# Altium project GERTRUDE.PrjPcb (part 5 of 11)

## Sheet ETH_PHY.SchDoc: ETH PHY
size A3; Author: Silvio Navaretti; CompanyName: ARDUINO; DrawnBy: Silvio Navaretti; Engineer: Silvio Navaretti; Organization: ARDUINO; SheetNumber: 36; SheetTotal: 51; RevAuthor: Silvio Navaretti
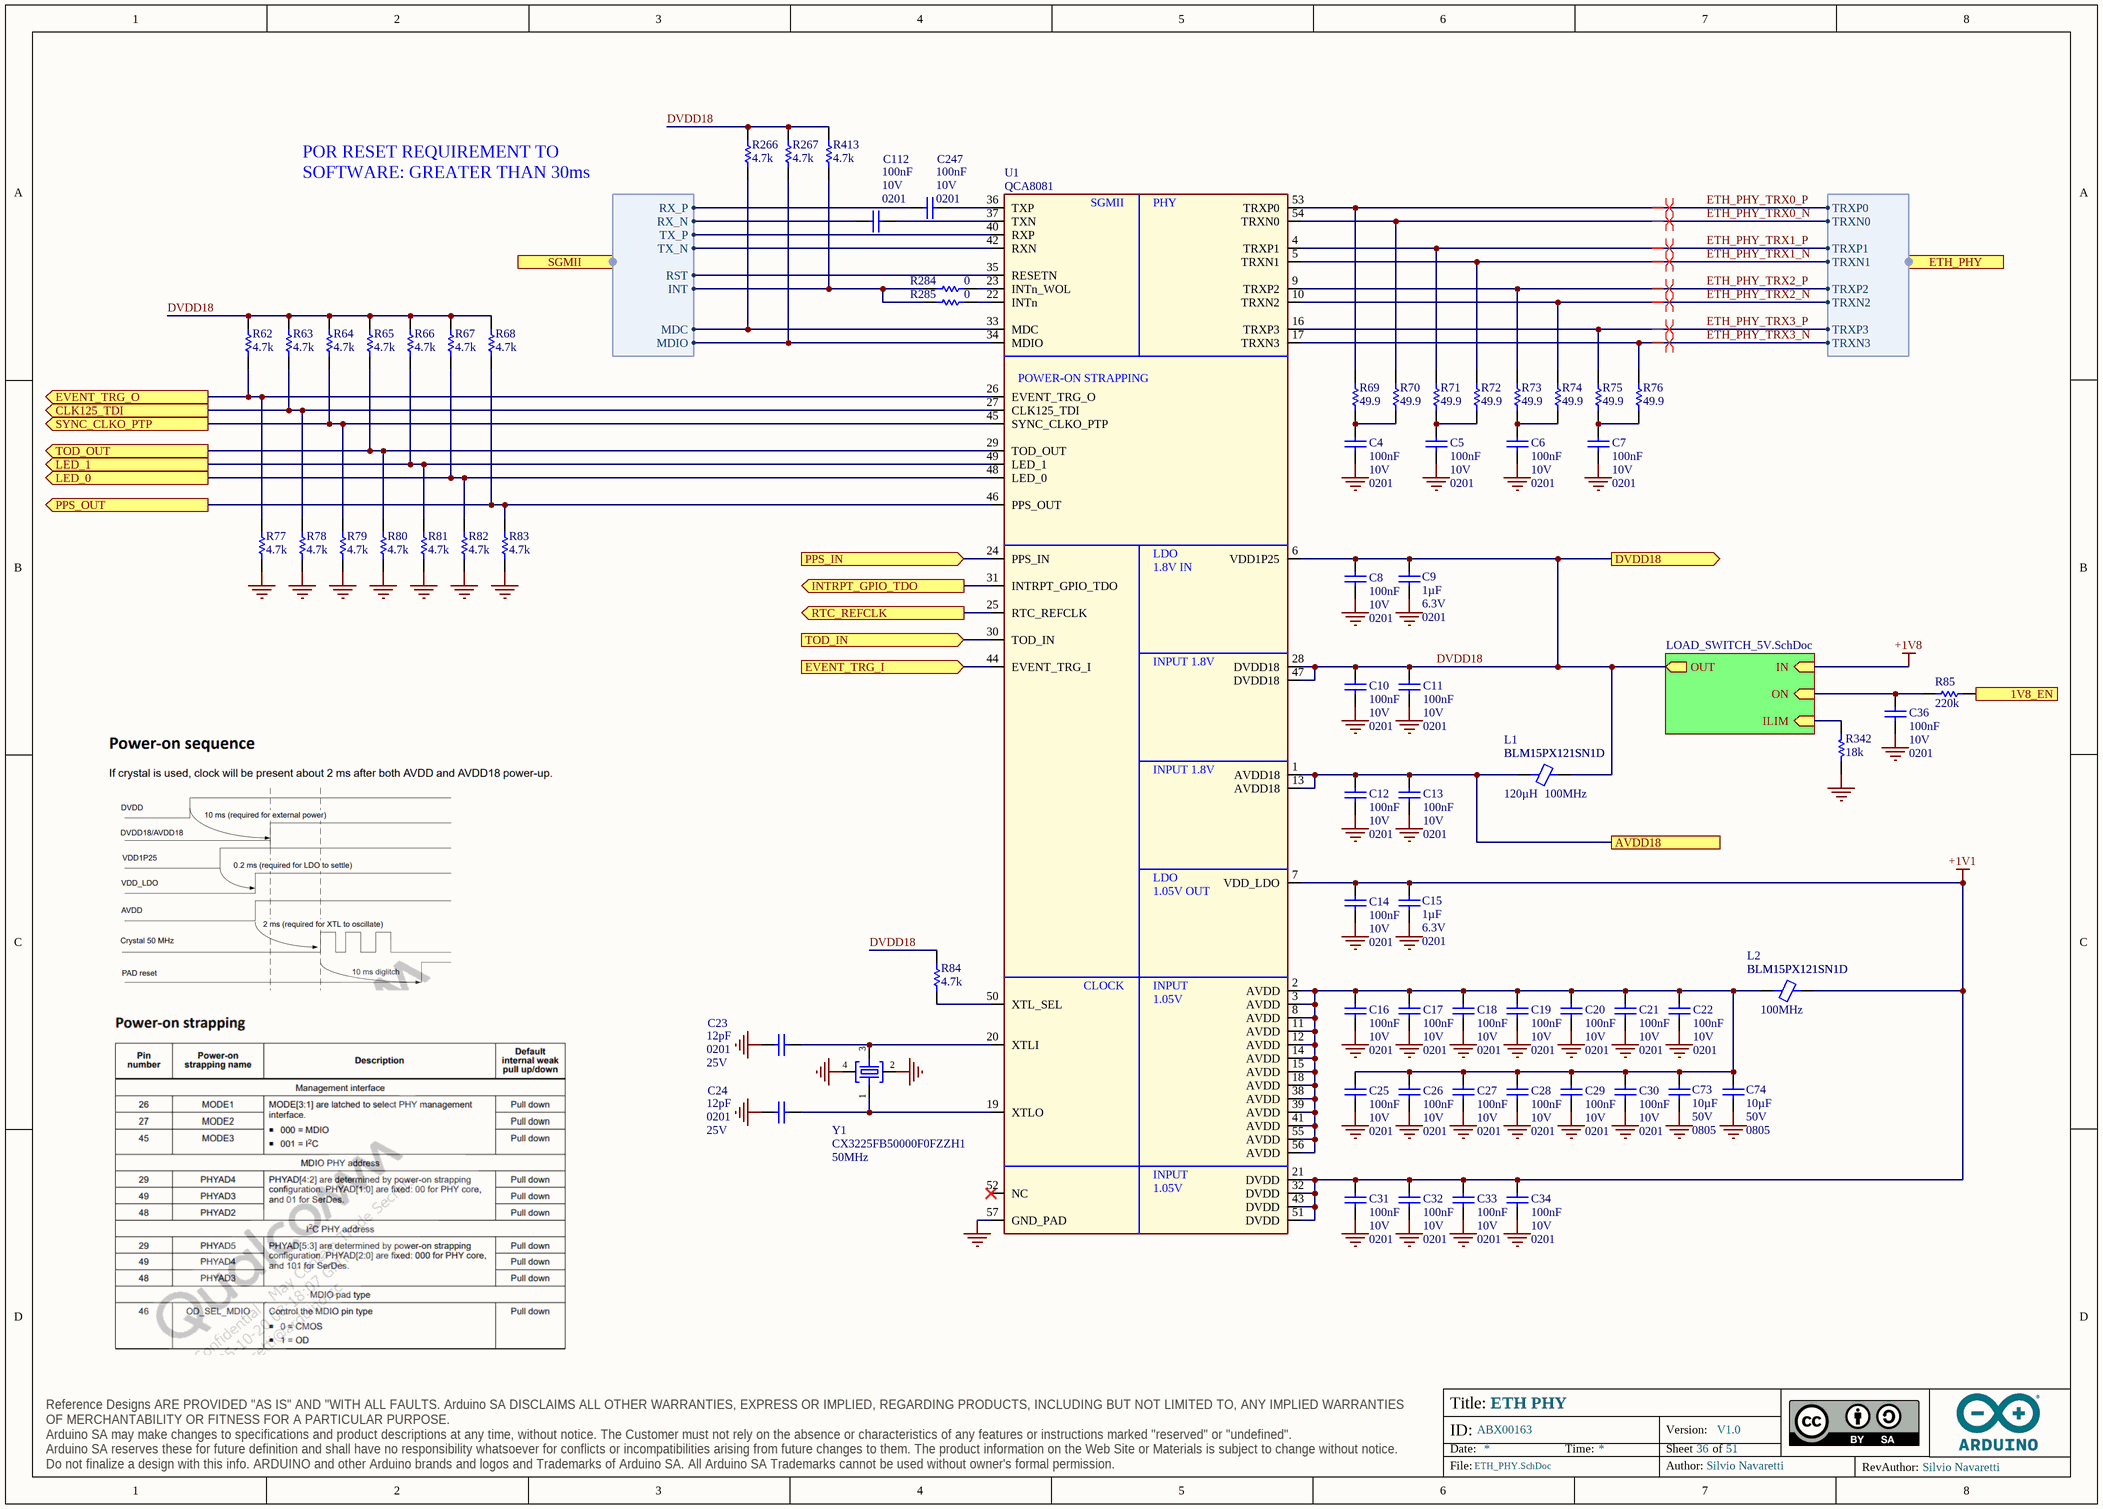
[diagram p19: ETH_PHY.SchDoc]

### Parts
C4  value 100nF  Voltage: 10V  Case Code (Imperial): 0201  [CAP-0201]  (hidden comment: CL03A104KP3NNNC)
C5  value 100nF  Voltage: 10V  Case Code (Imperial): 0201  [CAP-0201]  (hidden comment: CL03A104KP3NNNC)
C6  value 100nF  Voltage: 10V  Case Code (Imperial): 0201  [CAP-0201]  (hidden comment: CL03A104KP3NNNC)
C7  value 100nF  Voltage: 10V  Case Code (Imperial): 0201  [CAP-0201]  (hidden comment: CL03A104KP3NNNC)
C8  value 100nF  Voltage: 10V  Case Code (Imperial): 0201  [CAP-0201]  (hidden comment: CL03A104KP3NNNC)
C9  value 1µF  Voltage: 6.3V  Case Code (Imperial): 0201  [CAP-0201]  (hidden comment: GRM033R60J105MEA2D)
C10  value 100nF  Voltage: 10V  Case Code (Imperial): 0201  [CAP-0201]  (hidden comment: CL03A104KP3NNNC)
C11  value 100nF  Voltage: 10V  Case Code (Imperial): 0201  [CAP-0201]  (hidden comment: CL03A104KP3NNNC)
C12  value 100nF  Voltage: 10V  Case Code (Imperial): 0201  [CAP-0201]  (hidden comment: CL03A104KP3NNNC)
C13  value 100nF  Voltage: 10V  Case Code (Imperial): 0201  [CAP-0201]  (hidden comment: CL03A104KP3NNNC)
C14  value 100nF  Voltage: 10V  Case Code (Imperial): 0201  [CAP-0201]  (hidden comment: CL03A104KP3NNNC)
C15  value 1µF  Voltage: 6.3V  Case Code (Imperial): 0201  [CAP-0201]  (hidden comment: GRM033R60J105MEA2D)
C16  value 100nF  Voltage: 10V  Case Code (Imperial): 0201  [CAP-0201]  (hidden comment: CL03A104KP3NNNC)
C17  value 100nF  Voltage: 10V  Case Code (Imperial): 0201  [CAP-0201]  (hidden comment: CL03A104KP3NNNC)
C18  value 100nF  Voltage: 10V  Case Code (Imperial): 0201  [CAP-0201]  (hidden comment: CL03A104KP3NNNC)
C19  value 100nF  Voltage: 10V  Case Code (Imperial): 0201  [CAP-0201]  (hidden comment: CL03A104KP3NNNC)
C20  value 100nF  Voltage: 10V  Case Code (Imperial): 0201  [CAP-0201]  (hidden comment: CL03A104KP3NNNC)
C21  value 100nF  Voltage: 10V  Case Code (Imperial): 0201  [CAP-0201]  (hidden comment: CL03A104KP3NNNC)
C22  value 100nF  Voltage: 10V  Case Code (Imperial): 0201  [CAP-0201]  (hidden comment: CL03A104KP3NNNC)
C23  value 12pF  Case Code (Imperial): 0201  Voltage: 25V  [CAP-0201]  (hidden comment: GRM0335C1E120JA01J)
C24  value 12pF  Case Code (Imperial): 0201  Voltage: 25V  [CAP-0201]  (hidden comment: GRM0335C1E120JA01J)
C25  value 100nF  Voltage: 10V  Case Code (Imperial): 0201  [CAP-0201]  (hidden comment: CL03A104KP3NNNC)
C26  value 100nF  Voltage: 10V  Case Code (Imperial): 0201  [CAP-0201]  (hidden comment: CL03A104KP3NNNC)
C27  value 100nF  Voltage: 10V  Case Code (Imperial): 0201  [CAP-0201]  (hidden comment: CL03A104KP3NNNC)
C28  value 100nF  Voltage: 10V  Case Code (Imperial): 0201  [CAP-0201]  (hidden comment: CL03A104KP3NNNC)
C29  value 100nF  Voltage: 10V  Case Code (Imperial): 0201  [CAP-0201]  (hidden comment: CL03A104KP3NNNC)
C30  value 100nF  Voltage: 10V  Case Code (Imperial): 0201  [CAP-0201]  (hidden comment: CL03A104KP3NNNC)
C31  value 100nF  Voltage: 10V  Case Code (Imperial): 0201  [CAP-0201]  (hidden comment: CL03A104KP3NNNC)
C32  value 100nF  Voltage: 10V  Case Code (Imperial): 0201  [CAP-0201]  (hidden comment: CL03A104KP3NNNC)
C33  value 100nF  Voltage: 10V  Case Code (Imperial): 0201  [CAP-0201]  (hidden comment: CL03A104KP3NNNC)
C34  value 100nF  Voltage: 10V  Case Code (Imperial): 0201  [CAP-0201]  (hidden comment: CL03A104KP3NNNC)
C36  value 100nF  Voltage: 10V  Case Code (Imperial): 0201  [CAP-0201]  (hidden comment: CL03A104KP3NNNC)
C73  value 10µF  Voltage: 50V  Case Code (Imperial): 0805  [CAP-0805]  (hidden comment: GRM21BR61H106ME43L)
C74  value 10µF  Voltage: 50V  Case Code (Imperial): 0805  [CAP-0805]  (hidden comment: GRM21BR61H106ME43L)
C112  value 100nF  Voltage: 10V  Case Code (Imperial): 0201  [CAP-0201]  (hidden comment: CL03A104KP3NNNC)
C247  value 100nF  Voltage: 10V  Case Code (Imperial): 0201  [CAP-0201]  (hidden comment: CL03A104KP3NNNC)
L1  BLM15PX121SN1D  Inductance: 120µH  Test Frequency: 100MHz  [L-0402]
L2  BLM15PX121SN1D  Test Frequency: 100MHz  [L-0402]
R62  value 4.7k  [RES-0201]  (hidden comment: RC0201FR-074K7L)
R63  value 4.7k  [RES-0201]  (hidden comment: RC0201FR-074K7L)
R64  value 4.7k  [RES-0201]  (hidden comment: RC0201FR-074K7L)
R65  value 4.7k  [RES-0201]  (hidden comment: RC0201FR-074K7L)
R66  value 4.7k  [RES-0201]  (hidden comment: RC0201FR-074K7L)
R67  value 4.7k  [RES-0201]  (hidden comment: RC0201FR-074K7L)
R68  value 4.7k  [RES-0201]  (hidden comment: RC0201FR-074K7L)
R69  value 49.9  [RES-0201]  (hidden comment: AC0201FR-0749R9L)
R70  value 49.9  [RES-0201]  (hidden comment: AC0201FR-0749R9L)
R71  value 49.9  [RES-0201]  (hidden comment: AC0201FR-0749R9L)
R72  value 49.9  [RES-0201]  (hidden comment: AC0201FR-0749R9L)
R73  value 49.9  [RES-0201]  (hidden comment: AC0201FR-0749R9L)
R74  value 49.9  [RES-0201]  (hidden comment: AC0201FR-0749R9L)
R75  value 49.9  [RES-0201]  (hidden comment: AC0201FR-0749R9L)
R76  value 49.9  [RES-0201]  (hidden comment: AC0201FR-0749R9L)
R77  value 4.7k  [RES-0201]  (hidden comment: RC0201FR-074K7L)
R78  value 4.7k  [RES-0201]  (hidden comment: RC0201FR-074K7L)
R79  value 4.7k  [RES-0201]  (hidden comment: RC0201FR-074K7L)
R80  value 4.7k  [RES-0201]  (hidden comment: RC0201FR-074K7L)
R81  value 4.7k  [RES-0201]  (hidden comment: RC0201FR-074K7L)
R82  value 4.7k  [RES-0201]  (hidden comment: RC0201FR-074K7L)
R83  value 4.7k  [RES-0201]  (hidden comment: RC0201FR-074K7L)
R84  value 4.7k  [RES-0201]  (hidden comment: RC0201FR-074K7L)
R85  value 220k  [RES-0201]  (hidden comment: AC0201FR-07220KL)
R266  value 4.7k  [RES-0201]  (hidden comment: RC0201FR-074K7L)
R267  value 4.7k  [RES-0201]  (hidden comment: RC0201FR-074K7L)
R284  value 0  [RES-0201]  (hidden comment: CRCW02010000Z0ED)
R285  value 0  [RES-0201]  (hidden comment: CRCW02010000Z0ED)
R342  value 18k  [RES-0201]  (hidden comment: RC0201FR-0718KL)
R413  value 4.7k  [RES-0201]  (hidden comment: RC0201FR-074K7L)
U1  QCA8081  [Qualcomm QCA8081 56 MQFN 7x7mm pitch 0.4mm]
Y1  CX3225FB50000F0FZZH1  Frequency: 50MHz  [CRYSTAL3.2X2.5]

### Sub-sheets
U_LOAD_SWITCH_5V = LOAD_SWITCH_5V.SchDoc: IN (in), OUT (out), ON (in), ILIM (in)

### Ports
1V8_EN (in), AVDD18, CLK125_TDI (out), DVDD18 (out), ETH_PHY (harness ETH_QCA8081), EVENT_TRG_I (in), EVENT_TRG_O (out), INTRPT_GPIO_TDO (out), LED_0 (out), LED_1 (out), PPS_IN (in), PPS_OUT (out), RTC_REFCLK (out), SGMII (harness SOM_MD_SGMII0), SYNC_CLKO_PTP (out), TOD_IN (in), TOD_OUT (out)

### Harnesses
ETH_QCA8081: TRXP1, TRXN1, TRXP0, TRXN0, TRXP2, TRXN2, TRXP3, TRXN3
SOM_MD_SGMII0: RX_P, RX_N, TX_P, TX_N, RST, MDC, INT, MDIO

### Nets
+1V1: C14.2 C15.2 C31.2 C32.2 C33.2 C34.2 L2.2 U1.7(VDD_LDO) U1.21(DVDD) U1.32(DVDD) U1.43(DVDD) U1.51(DVDD)
GND: C4.1 C5.1 C6.1 C7.1 C8.1 C9.1 C10.1 C11.1 C12.1 C13.1 C14.1 C15.1 C16.1 C17.1 C18.1 C19.1 C20.1 C21.1 C22.1 C23.2 C24.2 C25.1 C26.1 C27.1 C28.1 C29.1 C30.1 C31.1 C32.1 C33.1 C34.1 C36.1 C73.2 C74.2 R77.1 R78.1 R79.1 R80.1 R81.1 R82.1 R83.1 R342.1 U1.57(GND_PAD) Y1.2 Y1.4
1V05_PG (PULLUP 1V8): R85.1 ; port 1V8_EN
DVDD18: C8.2 C9.2 C10.2 C11.2 L1.2 R62.2 R63.2 R64.2 R65.2 R66.2 R67.2 R68.2 R84.2 R266.2 R267.2 R413.2 U1.6(VDD1P25) U1.28(DVDD18) U1.47(DVDD18) ; port DVDD18, sheet U_LOAD_SWITCH_5V/OUT
ETH_PHY_TRX0_N: R70.2 U1.54(TRXN0) ; port ETH_PHY.TRXN0
ETH_PHY_TRX0_P: R69.2 U1.53(TRXP0) ; port ETH_PHY.TRXP0
ETH_PHY_TRX1_N: R72.2 U1.5(TRXN1) ; port ETH_PHY.TRXN1
ETH_PHY_TRX1_P: R71.2 U1.4(TRXP1) ; port ETH_PHY.TRXP1
ETH_PHY_TRX2_N: R74.2 U1.10(TRXN2) ; port ETH_PHY.TRXN2
ETH_PHY_TRX2_P: R73.2 U1.9(TRXP2) ; port ETH_PHY.TRXP2
ETH_PHY_TRX3_N: R76.2 U1.17(TRXN3) ; port ETH_PHY.TRXN3
ETH_PHY_TRX3_P: R75.2 U1.16(TRXP3) ; port ETH_PHY.TRXP3
GPIO_4: R284.1 R285.1 R413.1 ; port SGMII.INT
GPIO_5: R266.1 U1.33(MDC) ; port SGMII.MDC
GPIO_6: R267.1 U1.34(MDIO) ; port SGMII.MDIO
GPIO_50: U1.35(RESETN) ; port SGMII.RST
MD_SGMII0.RX_N: C112.2 ; port SGMII.RX_N
MD_SGMII0.RX_P: C247.2 ; port SGMII.RX_P
MD_SGMII0.TX_N: U1.42(RXN) ; port SGMII.TX_N
MD_SGMII0.TX_P: U1.40(RXP) ; port SGMII.TX_P
NetC4_2: C4.2 R69.1 R70.1
NetC5_2: C5.2 R71.1 R72.1
NetC6_2: C6.2 R73.1 R74.1
NetC7_2: C7.2 R75.1 R76.1
NetC12_2: C12.2 C13.2 L1.1 U1.1(AVDD18) U1.13(AVDD18) ; port AVDD18
NetC16_2: C16.2 C17.2 C18.2 C19.2 C20.2 C21.2 C22.2 C25.2 C26.2 C27.2 C28.2 C29.2 C30.2 C73.1 C74.1 L2.1 U1.2(AVDD) U1.3(AVDD) U1.8(AVDD) U1.11(AVDD) U1.12(AVDD) U1.14(AVDD) U1.15(AVDD) U1.18(AVDD) U1.38(AVDD) U1.39(AVDD) U1.41(AVDD) U1.55(AVDD) U1.56(AVDD)
NetC23_1: C23.1 U1.20(XTLI) Y1.3
NetC24_1: C24.1 U1.19(XTLO) Y1.1
NetC36_2: C36.2 R85.2 ; sheet U_LOAD_SWITCH_5V/ON
NetC112_1: C112.1 U1.37(TXN)
NetC247_1: C247.1 U1.36(TXP)
NetR62_1: R62.1 R77.2 U1.26(EVENT_TRG_O) ; port EVENT_TRG_O
NetR63_1: R63.1 R78.2 U1.27(CLK125_TDI) ; port CLK125_TDI
NetR64_1: R64.1 R79.2 U1.45(SYNC_CLKO_PTP) ; port SYNC_CLKO_PTP
NetR65_1: R65.1 R80.2 U1.29(TOD_OUT) ; port TOD_OUT
NetR66_1: R66.1 R81.2 U1.49(LED_1) ; port LED_1
NetR67_1: R67.1 R82.2 U1.48(LED_0) ; port LED_0
NetR68_1: R68.1 R83.2 U1.46(PPS_OUT) ; port PPS_OUT
NetR84_1: R84.1 U1.50(XTL_SEL)
NetR284_2: R284.2 U1.23(INTn_WOL)
NetR285_2: R285.2 U1.22(INTn)
NetR342_2: R342.2 ; sheet U_LOAD_SWITCH_5V/ILIM
NetTP40_X: U1.44(EVENT_TRG_I) ; port EVENT_TRG_I
NetTP41_X: U1.30(TOD_IN) ; port TOD_IN
NetTP42_X: U1.24(PPS_IN) ; port PPS_IN
NetTP43_X: U1.25(RTC_REFCLK) ; port RTC_REFCLK
NetTP49_X: U1.31(INTRPT_GPIO_TDO) ; port INTRPT_GPIO_TDO

Not connected (* = marked no-connect by the designer): U1 52(NC)*

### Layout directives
differential pair; differential pair class DIFF_ETHPHY; net class DIFF_ETHPHY: ETH_PHY_TRX0_N, ETH_PHY_TRX0_P, ETH_PHY_TRX1_N, ETH_PHY_TRX1_P, ETH_PHY_TRX2_N, ETH_PHY_TRX2_P, ETH_PHY_TRX3_N, ETH_PHY_TRX3_P

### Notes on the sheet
- POR RESET REQUIREMENT TO SOFTWARE: GREATER THAN 30ms

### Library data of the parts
C4-C8 C10-C14 C16-C22 C25-C34 C36 C112 C247 = C0113-A.6: CAP CHIP 0201 100nF 10% 10V X5R; Manufacturer: Samsung Electro-Mechanics; Code Arduino: C0113
C9 C15 = C0002-A.15: CAP CHIP 0201 1uF 20% 6.3V X5R; Manufacturer: Murata; Code Arduino: A5520
C23 C24 = C0003-A.15: CAP CHIP 0201 12pF 5% 25V C0G; Manufacturer: Murata; Code Arduino: C0003
C73 C74 = C0158-A.3: CAP CHIP 0805 10uF 20% 50V X5R; Manufacturer: Murata Electronics; Code Arduino: C0158
L1 = I0028-A.10: FERRITE SMD 0402 120Ohm 25% 100MHz Ferrite 2A; Manufacturer: Murata; DC Resistance (DCR): 55mR; Code Arduino: I0028; Value: 120µH
L2 = I0028-A.10: FERRITE SMD 0402 120Ohm 25% 100MHz Ferrite 2A; Manufacturer: Murata; Inductance: 120µH; DC Resistance (DCR): 55mR; Code Arduino: I0028; Value: 120µH
R62-R68 R77-R84 R266 R267 R413 = R0151-A.21: RES CHIP 0201 4k7 1% 1/20W; Manufacturer: Yageo; Temperature coefficient: 200ppm; Power: 50mW; Code Arduino: A5521
R69-R76 = R0152-A.22: RES CHIP 0201 49R9 1% 1/20W; Manufacturer: Yageo; Temperature coefficient: 200ppm; Power: 50mW; Code Arduino: R0152
R85 = R0199-A.20: RES CHIP 0201 220k 1% 1/20W; Manufacturer: Yageo; Temperature coefficient: 200ppm; Power: 50mW; Code Arduino: R0199
R284 R285 = R0140-A.21: RES CHIP 0201 0R; Manufacturer: Vishay; Temperature coefficient: 0ppm; Code Arduino: R0140; Power: 50mW; Tolerance: 0%
R342 = R0399-A.1: RES CHIP 0201 18k 1% 1/20W; Manufacturer: YAGEO; Power: 50mW; Code Arduino: R0399; Temperature Coefficient: 200ppm
U1 = U0492-A.6: IC ETH PHY 2.5Gb, 7x7mm MQFN56; Manufacturer: Qualcomm; Code Arduino: U0492
Y1 = X0031-A.3: CRYSTAL 50MHz tolerance 10ppm stability 20ppm load 10pF 3.2x2.5mm; Manufacturer: Kyocera; Code Arduino: X0031; Series Resistance: 22R

## Sheet ETH_RJ45.SchDoc: ETH RJ45
size A3; Author: Silvio Navaretti; CompanyName: ARDUINO; DrawnBy: Silvio Navaretti; Engineer: Silvio Navaretti; Organization: ARDUINO; SheetNumber: 37; SheetTotal: 51; RevAuthor: Silvio Navaretti
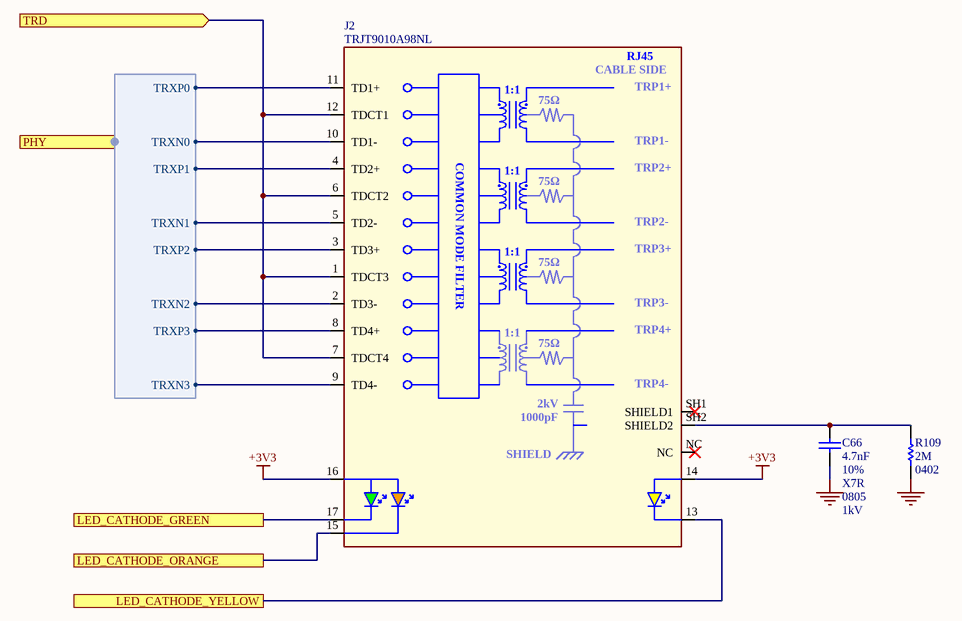
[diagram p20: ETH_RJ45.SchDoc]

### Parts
C66  value 4.7nF  Tolerance: 10%  Dielectric: X7R  Case Code (Imperial): 0805  Voltage: 1kV  [CAP-0805]  (hidden comment: FV21X472K102ECG)
J2  TRJT9010A98NL  [TRJT9010A98NL]
R109  value 2M  Case Code (Imperial): 0402  [RES-0402]  (hidden comment: RC0402FR-072ML)

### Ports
LED_CATHODE_GREEN, LED_CATHODE_ORANGE, LED_CATHODE_YELLOW, PHY (harness ETH_QCA8081), TRD (in)

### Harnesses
ETH_QCA8081: TRXP1, TRXN1, TRXP0, TRXN0, TRXP2, TRXN2, TRXP3, TRXN3

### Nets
+3V3: J2.14(YELLOW_ANODE) J2.16(COMMON_ANODE)
GND: C66.2 R109.1
ETH_PHY_TRX0_N: J2.10(TD1-) ; port PHY.TRXN0
ETH_PHY_TRX0_P: J2.11(TD1+) ; port PHY.TRXP0
ETH_PHY_TRX1_N: J2.5(TD2-) ; port PHY.TRXN1
ETH_PHY_TRX1_P: J2.4(TD2+) ; port PHY.TRXP1
ETH_PHY_TRX2_N: J2.2(TD3-) ; port PHY.TRXN2
ETH_PHY_TRX2_P: J2.3(TD3+) ; port PHY.TRXP2
ETH_PHY_TRX3_N: J2.9(TD4-) ; port PHY.TRXN3
ETH_PHY_TRX3_P: J2.8(TD4+) ; port PHY.TRXP3
NetC12_2: J2.1(TDCT3) J2.6(TDCT2) J2.7(TDCT4) J2.12(TDCT1) ; port TRD
NetC66_1: C66.1 J2.SH2(SHIELD2) R109.2
NetJ2_13: J2.13(YELLOW_CATHODE) ; port LED_CATHODE_YELLOW
NetJ2_15: J2.15(ORANGE_CATHODE) ; port LED_CATHODE_ORANGE
NetJ2_17: J2.17(GREEN_CATHODE) ; port LED_CATHODE_GREEN

Not connected (* = marked no-connect by the designer): J2 NC* SH1(SHIELD1)*

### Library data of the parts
C66 = C0059-A.14: CAP CHIP 0805 4.7nF 10% 1000V X7R; Manufacturer: PSA Shenzen; Code Arduino: 0689
J2 = J0561-A.4: CONN ETH 1x1 RJ45 TH 10/100/1000/2500 integrated magnetics, LED GREEN/YELLOW/ORANGE, micro profile 17.8x24.2x11.55mm; Manufacturer: TRXCOM; Code Arduino: J0561
R109 = R0394-A.1: RES CHIP 0402 2M 1% 1/16W; Manufacturer: YAGEO; Temperature coefficient: 100ppm; Code Arduino: R0394; Power: 62.5mW

## Sheet HEADERS_UNO.SchDoc: HEADERS UNO
size A3; Author: Silvio Navaretti; CompanyName: ARDUINO; DrawnBy: Silvio Navaretti; Engineer: Silvio Navaretti; Organization: ARDUINO; SheetNumber: 19; SheetTotal: 51; RevAuthor: Silvio Navaretti
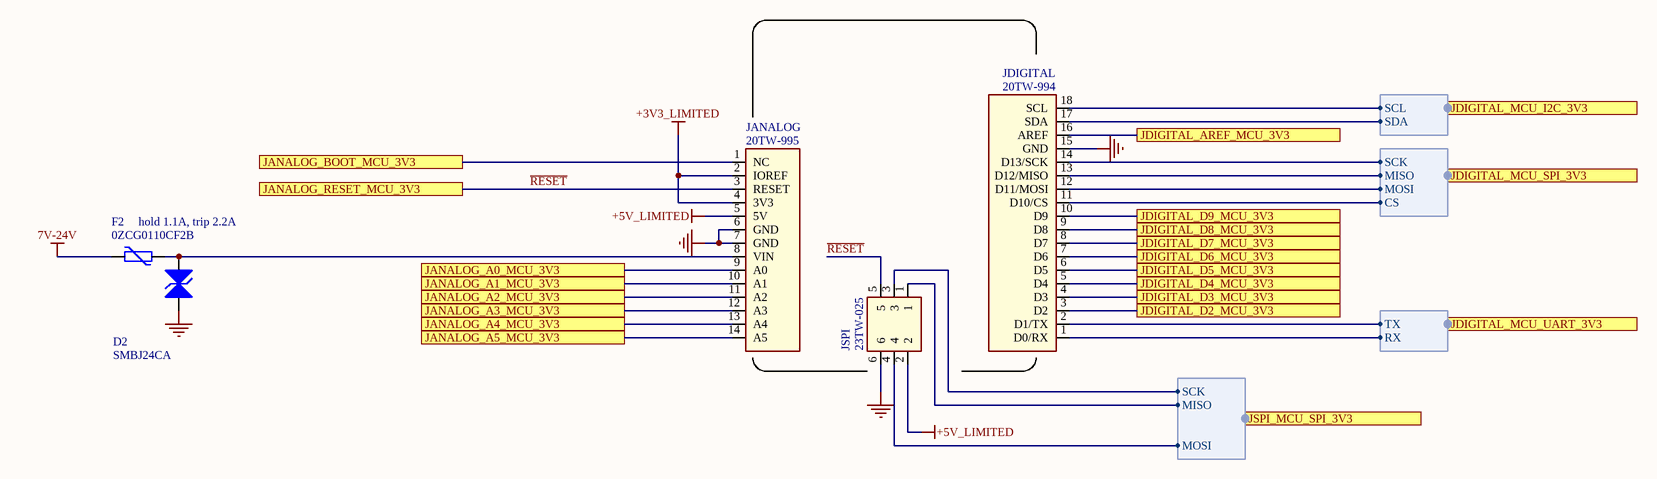
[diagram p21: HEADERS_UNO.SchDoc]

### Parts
D2  SMBJ24CA  [SMB_NOPOLARITY]
F2  0ZCG0110CF2B  [1812]
JANALOG  20TW-995  [1X14-CUSTOM]
JDIGITAL  20TW-994  [1X18-CUSTOM]
JSPI  23TW-025  [23TW-025]

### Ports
JANALOG_A0_MCU_3V3, JANALOG_A1_MCU_3V3, JANALOG_A2_MCU_3V3, JANALOG_A3_MCU_3V3, JANALOG_A4_MCU_3V3, JANALOG_A5_MCU_3V3, JANALOG_BOOT_MCU_3V3, JANALOG_RESET_MCU_3V3, JDIGITAL_AREF_MCU_3V3, JDIGITAL_D2_MCU_3V3, JDIGITAL_D3_MCU_3V3, JDIGITAL_D4_MCU_3V3, JDIGITAL_D5_MCU_3V3, JDIGITAL_D6_MCU_3V3, JDIGITAL_D7_MCU_3V3, JDIGITAL_D8_MCU_3V3, JDIGITAL_D9_MCU_3V3, JDIGITAL_MCU_I2C_3V3 (harness I2C), JDIGITAL_MCU_SPI_3V3 (harness SPI), JDIGITAL_MCU_UART_3V3 (harness UART), JSPI_MCU_SPI_3V3 (harness JSPI_SPI)

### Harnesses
SPI: SCK, MISO, MOSI, CS
UART: TX, RX
I2C: SDA, SCL
JSPI_SPI: SCK, MISO, MOSI

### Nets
7V-24V: F2.1
+3V3_LIMITED: JANALOG.2(IOREF) JANALOG.4(3V3)
+5V_LIMITED: JANALOG.5(5V) JSPI.2
GND: D2.1(A1) JANALOG.6(GND) JANALOG.7(GND) JDIGITAL.15(GND) JSPI.6
BOOT0: JANALOG.1(NC) ; port JANALOG_BOOT_MCU_3V3
PA4: JANALOG.9(A0) ; port JANALOG_A0_MCU_3V3
PA5: JANALOG.10(A1) ; port JANALOG_A1_MCU_3V3
PB0: JDIGITAL.3(D2) ; port JDIGITAL_D2_MCU_3V3
PB1: JDIGITAL.4(D3) ; port JDIGITAL_D3_MCU_3V3
PB2: JDIGITAL.7(D6) ; port JDIGITAL_D6_MCU_3V3
PB3: JDIGITAL.8(D7) ; port JDIGITAL_D7_MCU_3V3
PB4: JDIGITAL.9(D8) ; port JDIGITAL_D8_MCU_3V3
PB5: JDIGITAL.6(D5) ; port JDIGITAL_D5_MCU_3V3
PB6: JDIGITAL.5(D4) ; port JDIGITAL_D4_MCU_3V3
PB7: JDIGITAL.10(D9) ; port JDIGITAL_D9_MCU_3V3
PB10: JDIGITAL.2(D1/TX) ; port JDIGITAL_MCU_UART_3V3.TX
PB11: JDIGITAL.1(D0/RX) ; port JDIGITAL_MCU_UART_3V3.RX
PB12: JDIGITAL.11(D10/CS) ; port JDIGITAL_MCU_SPI_3V3.CS
PB13: JDIGITAL.14(D13/SCK) ; port JDIGITAL_MCU_SPI_3V3.SCK
PB14: JDIGITAL.13(D12/MISO) ; port JDIGITAL_MCU_SPI_3V3.MISO
PB15: JDIGITAL.12(D11/MOSI) ; port JDIGITAL_MCU_SPI_3V3.MOSI
PC10: JSPI.3 ; port JSPI_MCU_SPI_3V3.SCK
PC12: JSPI.4 ; port JSPI_MCU_SPI_3V3.MOSI
PE12: JANALOG.11(A2) ; port JANALOG_A2_MCU_3V3
PE13: JANALOG.12(A3) ; port JANALOG_A3_MCU_3V3
PE14: JANALOG.13(A4) ; port JANALOG_A4_MCU_3V3
PE15: JANALOG.14(A5) ; port JANALOG_A5_MCU_3V3
PF14: JSPI.1 ; port JSPI_MCU_SPI_3V3.MISO
PH11: JDIGITAL.18(SCL) ; port JDIGITAL_MCU_I2C_3V3.SCL
PH12: JDIGITAL.17(SDA) ; port JDIGITAL_MCU_I2C_3V3.SDA
~{RESET}: JANALOG.3(RESET) JSPI.5 ; port JANALOG_RESET_MCU_3V3  [project net NRST]
NetC107_2: JDIGITAL.16(AREF) ; port JDIGITAL_AREF_MCU_3V3
NetD2_2: D2.2(A2) F2.2 JANALOG.8(VIN)

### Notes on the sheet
- hold 1.1A, trip 2.2A

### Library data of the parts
D2 = D0070-A.2: TVS BIDIRECTIONAL SMD Vr 24V, Vbr min 26.7V, 600W, SMB; Manufacturer: Littlefuse; V(BR) Typ (V): 26.7; Code Arduino: D0070
F2 = P0027-A.1: PTC Ihold 1.1A Itrip 2.2A 33V 1812; Manufacturer: Bel Fuse; Code Arduino: P0027
JANALOG = J0063-A.10: JANALOG UNO header 2.54mm with 8+6 pins, custom 5.08mm pitch between them, custom silkscreen print on side; Manufacturer: 4UCONN; Code Arduino: 3649
JDIGITAL = J0035-A.13: JDIGITAL UNO header 2.54mm with 8+10 pins, custom 4.06mm pitch between them, custom silkscreen print on side; Manufacturer: 4UCONN; Code Arduino: 3648
JSPI = J0569-A.3: CONN HEADER MALE 6POS 2x3 2.54mm SMD; Manufacturer: 4UCONN; Number of Contacts: 6; Code Arduino: J0569

## Sheet POWER.SchDoc: POWER
size A3; Author: Silvio Navaretti; CompanyName: ARDUINO; DrawnBy: Silvio Navaretti; Engineer: Silvio Navaretti; Organization: ARDUINO; SheetNumber: 38; SheetTotal: 51; RevAuthor: Silvio Navaretti
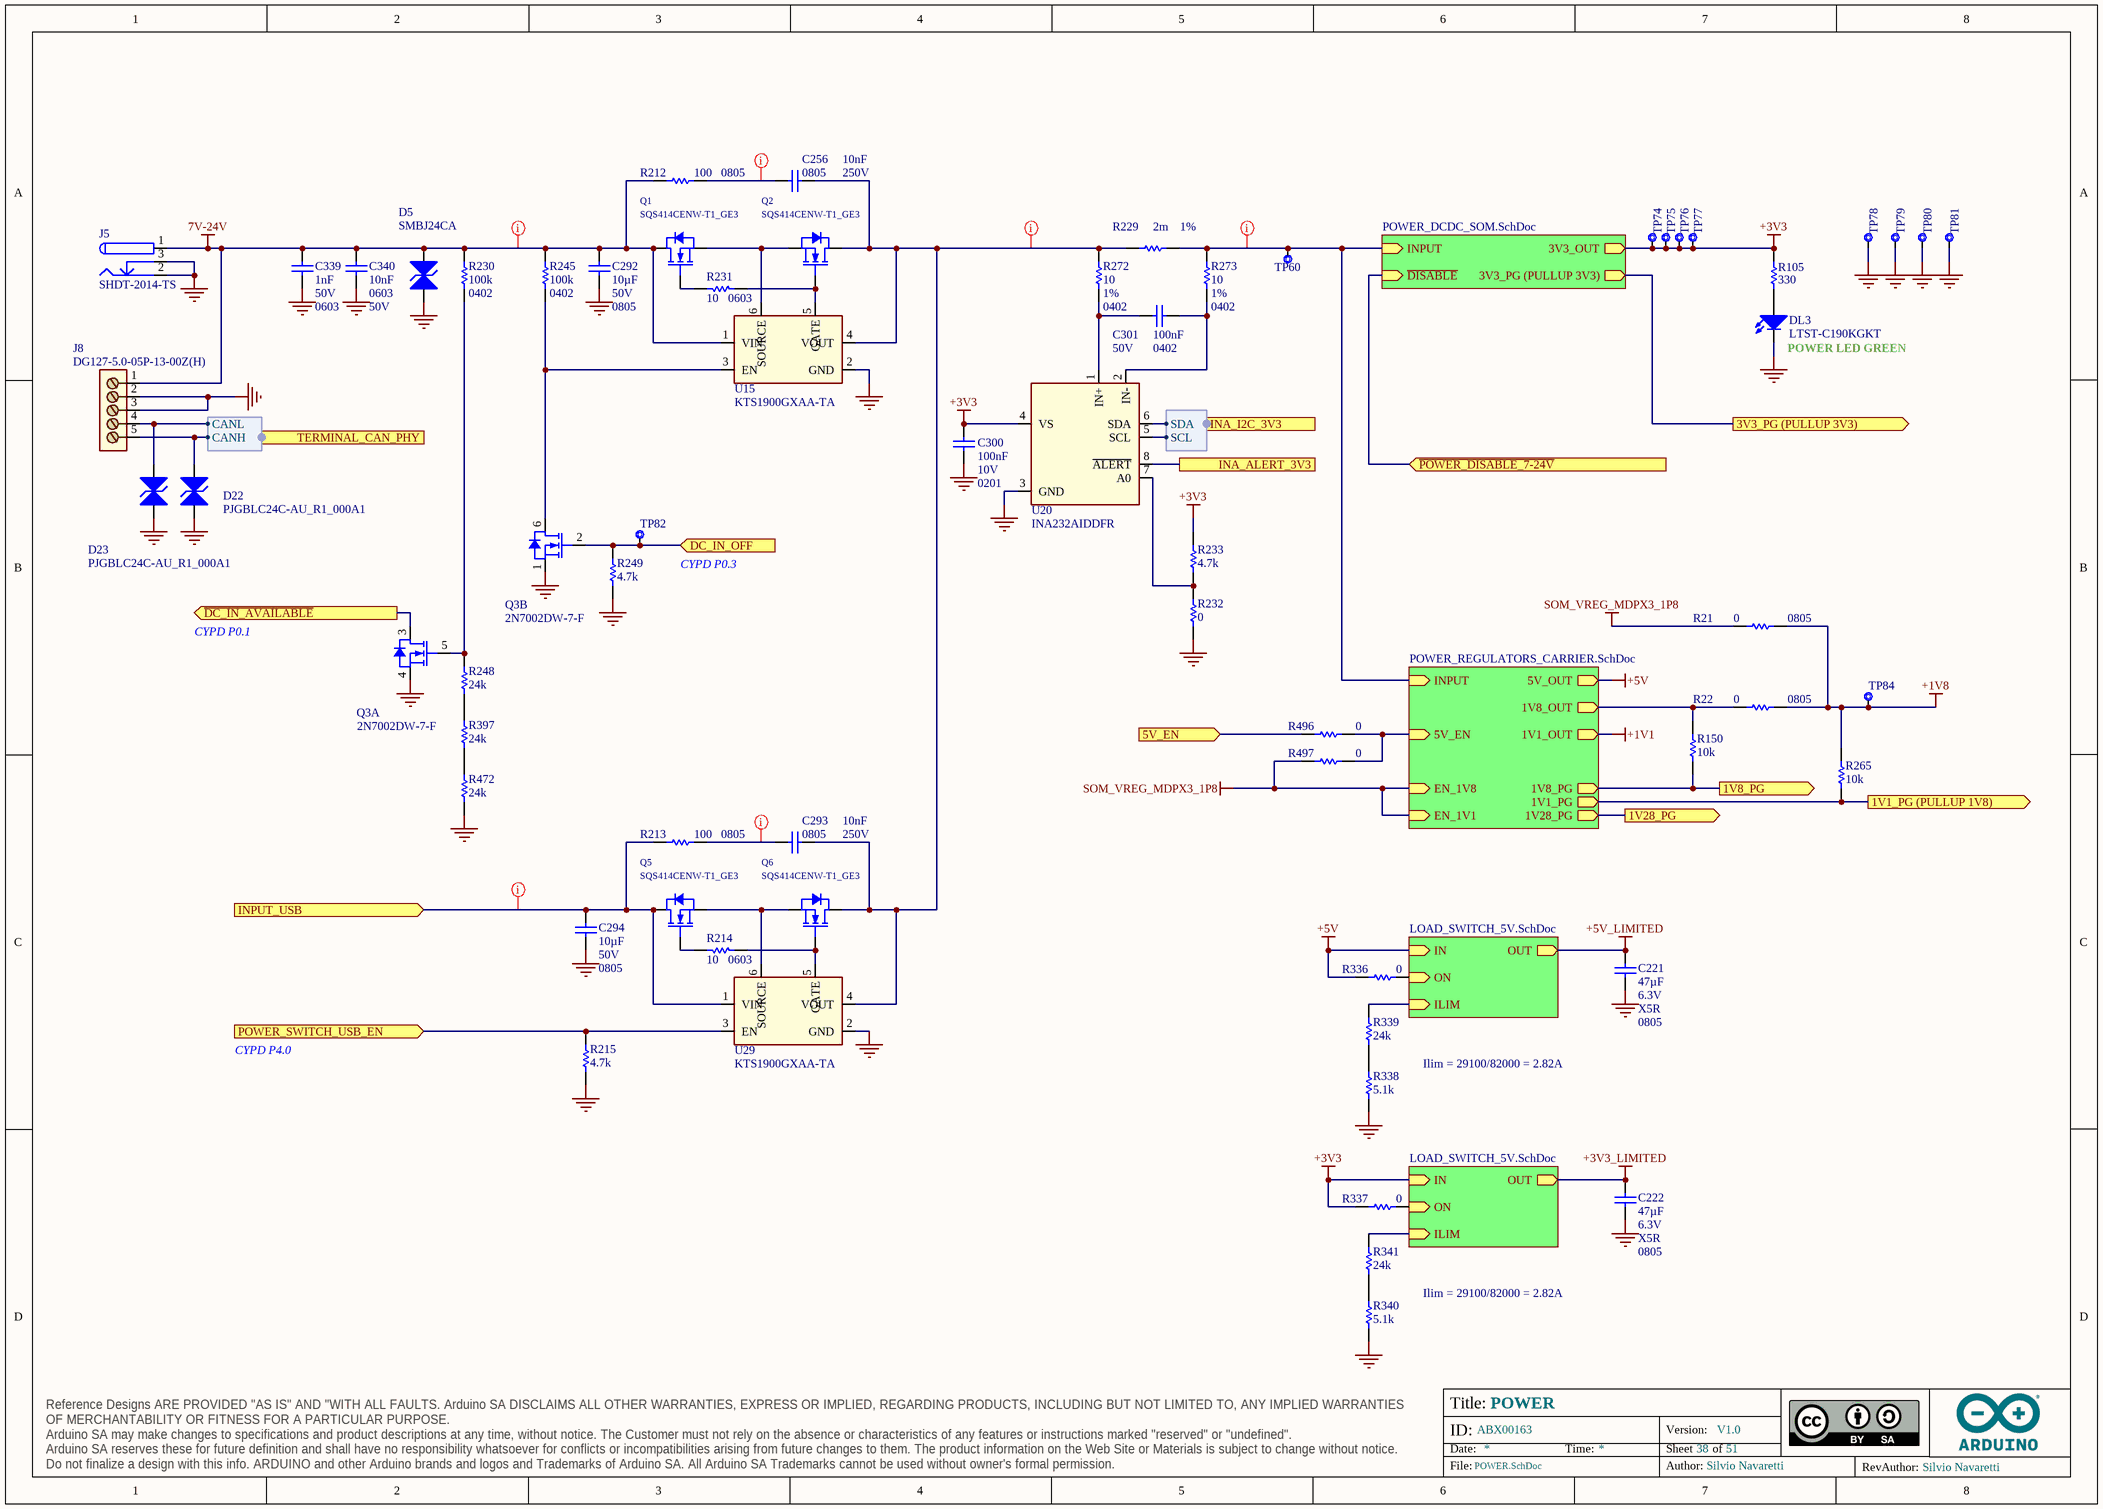
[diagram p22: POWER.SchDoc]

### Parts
C221  value 47µF  Voltage: 6.3V  Dielectric: X5R  Case Code (Imperial): 0805  [CAP-0805]  (hidden comment: C0805C476M9PAC7800)
C222  value 47µF  Voltage: 6.3V  Dielectric: X5R  Case Code (Imperial): 0805  [CAP-0805]  (hidden comment: C0805C476M9PAC7800)
C256  value 10nF  Case Code (Imperial): 0805  Voltage: 250V  [CAP-0805]  (hidden comment: GRM21BR72E103KW03L)
C292  value 10µF  Voltage: 50V  Case Code (Imperial): 0805  [CAP-0805]  (hidden comment: GRM21BR61H106ME43L)
C293  value 10nF  Case Code (Imperial): 0805  Voltage: 250V  [CAP-0805]  (hidden comment: GRM21BR72E103KW03L)
C294  value 10µF  Voltage: 50V  Case Code (Imperial): 0805  [CAP-0805]  (hidden comment: GRM21BR61H106ME43L)
C300  value 100nF  Voltage: 10V  Case Code (Imperial): 0201  [CAP-0201]  (hidden comment: CL03A104KP3NNNC)
C301  value 100nF  Voltage: 50V  Case Code (Imperial): 0402  [CAP-0402]  (hidden comment: GRM155R61H104KE19D)
C339  value 1nF  Voltage: 50V  Case Code (Imperial): 0603  [CAP-0603]  (hidden comment: CL10B102KB8WPNC)
C340  value 10nF  Case Code (Imperial): 0603  Voltage: 50V  [CAP-0603]  (hidden comment: 0603B103K500CT)
D5  SMBJ24CA  [SMB_NOPOLARITY]
D22  PJGBLC24C-AU_R1_000A1  [SOD323 NO POLARITY]
D23  PJGBLC24C-AU_R1_000A1  [SOD323 NO POLARITY]
DL3  LTST-C190KGKT  [LEDC1608X80N-AK]
J5  SHDT-2014-TS  [SHDT-2014-TS]
J8  DG127-5.0-05P-13-00Z(H)  [DG127-5.0-05P-13-00Z(H)]
Q1  SQS414CENW-T1_GE3  [SQS414CENW-T1_GE3]
Q2  SQS414CENW-T1_GE3  [SQS414CENW-T1_GE3]
Q3  2N7002DW-7-F  [SOT363]  (parts A,B of 2)
Q5  SQS414CENW-T1_GE3  [SQS414CENW-T1_GE3]
Q6  SQS414CENW-T1_GE3  [SQS414CENW-T1_GE3]
R21  value 0  Case Code (Imperial): 0805  [RES-0805]  (hidden comment: RC0805FR-070RL)
R22  value 0  Case Code (Imperial): 0805  [RES-0805]  (hidden comment: RC0805FR-070RL)
R105  value 330  [RES-0201]  (hidden comment: AC0201FR-07330RL)
R150  value 10k  [RES-0201]  (hidden comment: RC0201FR-0710KL)
R212  value 100  Case Code (Imperial): 0805  [RES-0805]  (hidden comment: RC0805FR-07100RL)
R213  value 100  Case Code (Imperial): 0805  [RES-0805]  (hidden comment: RC0805FR-07100RL)
R214  value 10  Case Code (Imperial): 0603  [RES-0603]  (hidden comment: CRCW060310R0FKEAC)
R215  value 4.7k  [RES-0201]  (hidden comment: RC0201FR-074K7L)
R229  value 2m  Tolerance: 1%  [RES-0805]  (hidden comment: PMR10EZPFV2L00)
R230  value 100k  Case Code (Imperial): 0402  [RES-0402]  (hidden comment: CRCW0402100KFKEDC)
R231  value 10  Case Code (Imperial): 0603  [RES-0603]  (hidden comment: CRCW060310R0FKEAC)
R232  value 0  [RES-0201]  (hidden comment: CRCW02010000Z0ED)
R233  value 4.7k  [RES-0201]  (hidden comment: RC0201FR-074K7L)
R245  value 100k  Case Code (Imperial): 0402  [RES-0402]  (hidden comment: CRCW0402100KFKEDC)
R248  value 24k  [RES-0201]  (hidden comment: RC0201FR-0724KL)
R249  value 4.7k  [RES-0201]  (hidden comment: RC0201FR-074K7L)
R265  value 10k  [RES-0201]  (hidden comment: RC0201FR-0710KL)
R272  value 10  Tolerance: 1%  Case Code (Imperial): 0402  [RES-0402]  (hidden comment: RC0402FR-0710RL)
R273  value 10  Tolerance: 1%  Case Code (Imperial): 0402  [RES-0402]  (hidden comment: RC0402FR-0710RL)
R336  value 0  [RES-0201]  (hidden comment: CRCW02010000Z0ED)
R337  value 0  [RES-0201]  (hidden comment: CRCW02010000Z0ED)
R338  value 5.1k  [RES-0201]  (hidden comment: ERJ-1GNF5101C)
R339  value 24k  [RES-0201]  (hidden comment: RC0201FR-0724KL)
R340  value 5.1k  [RES-0201]  (hidden comment: ERJ-1GNF5101C)
R341  value 24k  [RES-0201]  (hidden comment: RC0201FR-0724KL)
R397  value 24k  [RES-0201]  (hidden comment: RC0201FR-0724KL)
R472  value 24k  [RES-0201]  (hidden comment: RC0201FR-0724KL)
R496  value 0  [RES-0201]  (hidden comment: CRCW02010000Z0ED)
R497  value 0  [RES-0201]  (hidden comment: CRCW02010000Z0ED)
TP60  Test point 1.00mm  [TP-1.00MM]  (value not drawn)  (no BOM)
TP74  Test point 1.00mm  [TP-1.00MM]  (value not drawn)  (no BOM)
TP75  Test point 1.00mm  [TP-1.00MM]  (value not drawn)  (no BOM)
TP76  Test point 1.00mm  [TP-1.00MM]  (value not drawn)  (no BOM)
TP77  Test point 1.00mm  [TP-1.00MM]  (value not drawn)  (no BOM)
TP78  Test point 1.00mm  [TP-1.00MM]  (value not drawn)  (no BOM)
TP79  Test point 1.00mm  [TP-1.00MM]  (value not drawn)  (no BOM)
TP80  Test point 1.00mm  [TP-1.00MM]  (value not drawn)  (no BOM)
TP81  Test point 1.00mm  [TP-1.00MM]  (value not drawn)  (no BOM)
TP82  Test point 1.00mm  [TP-1.00MM]  (value not drawn)  (no BOM)
TP84  Test point 1.00mm  [TP-1.00MM]  (value not drawn)  (no BOM)
U15  KTS1900GXAA-TA  [SOT23-6 PITCH 0.95]
U20  INA232AIDDFR  [TI DDF SOT23-THIN 8 pin 1.6x2.9x1.1 mm heigth]
U29  KTS1900GXAA-TA  [SOT23-6 PITCH 0.95]

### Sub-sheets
U_LOAD_SWITCH_5V = LOAD_SWITCH_5V.SchDoc: IN (in), OUT (out), ON (in), ILIM (in)
U_LOAD_SWITCH_5V = LOAD_SWITCH_5V.SchDoc: IN (in), OUT (out), ON (in), ILIM (in)
U_POWER_DCDC_CARRIER = POWER_REGULATORS_CARRIER.SchDoc: INPUT (in), 5V_EN (in), 1V8_PG (out), 1V8_OUT (out), 1V1_OUT (out), 5V_OUT (out), 1V28_PG (out), 1V1_PG (out), EN_1V8 (in), EN_1V1 (in)
U_POWER_SOM = POWER_DCDC_SOM.SchDoc: 3V3_OUT (out), INPUT (in), ~{DISABLE} (in), 3V3_PG (PULLUP 3V3) (out)

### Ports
1V1_PG (PULLUP 1V8) (out), 1V8_PG (out), 1V28_PG (out), 3V3_PG (PULLUP 3V3) (out), 5V_EN (in), DC_IN_OFF (in), INA_ALERT_3V3, INA_I2C_3V3 (harness I2C), INPUT_USB (in), POWER_SWITCH_USB_EN (in), TERMINAL_CAN_PHY (harness CAN_PHY), ~{DC_IN_AVAILABLE} (out), ~{POWER_DISABLE_7-24V} (in)

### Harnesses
CAN_PHY: CANH, CANL
I2C: SDA, SCL

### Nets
7V-24V: C292.2 C339.1 C340.1 D5.2(A2) J5.1 J8.1 Q1.D R212.2 R230.1 R245.1 U15.1(VIN)
+1V8: R21.2 R22.2 R265.1 TP84.X
+3V3: C300.2 R105.2 R233.1 R337.1 TP74.X TP75.X TP76.X TP77.X U20.4(VS) ; sheet U_POWER_SOM/3V3_OUT, sheet U_LOAD_SWITCH_5V/IN
+3V3_LIMITED: C222.2 ; sheet U_LOAD_SWITCH_5V/OUT
+5V: R336.1 ; sheet U_POWER_DCDC_CARRIER/5V_OUT, sheet U_LOAD_SWITCH_5V/IN
+5V_LIMITED: C221.2 ; sheet U_LOAD_SWITCH_5V/OUT
GND: C221.1 C222.1 C292.1 C294.1 C300.1 C339.2 C340.2 D5.1(A1) D22.1(A1) D23.1(A1) DL3.C J5.2 J5.3 J8.2 J8.3 Q3.1(S) Q3.4(S) R215.2 R232.1 R249.2 R338.1 R340.1 R472.1 TP78.X TP79.X TP80.X TP81.X U15.2(GND) U20.3(GND) U29.2(GND)
SOM_VREG_MDPX3_1P8: R21.1 R497.2 ; sheet U_POWER_DCDC_CARRIER/EN_1V8, sheet U_POWER_DCDC_CARRIER/EN_1V1
1V05_PG (PULLUP 1V8): R265.2 ; port 1V1_PG (PULLUP 1V8), sheet U_POWER_DCDC_CARRIER/1V1_PG
3V3_PG (PULLUP 3V3): port 3V3_PG (PULLUP 3V3), sheet U_POWER_SOM/3V3_PG (PULLUP 3V3)
MD_GPIO_49: R496.2 ; port 5V_EN
MD_QUP1_SE4_I2C_3V3.SCL: U20.5(SCL) ; port INA_I2C_3V3.SCL
MD_QUP1_SE4_I2C_3V3.SDA: U20.6(SDA) ; port INA_I2C_3V3.SDA
~{POWER_DISABLE_7-24V}: port ~{POWER_DISABLE_7-24V}, sheet U_POWER_SOM/~{DISABLE}
PA_VBUS: C294.2 Q5.D R213.2 U29.1(VIN) ; port INPUT_USB
NetC76_1: R229.2 R273.2 TP60.X ; sheet U_POWER_SOM/INPUT, sheet U_POWER_DCDC_CARRIER/INPUT
NetC119_2: R22.1 R150.1 ; sheet U_POWER_DCDC_CARRIER/1V8_OUT
NetC256_1: C256.1 R212.1
NetC256_2: C256.2 C293.2 Q2.D Q6.D R229.1 R272.2 U15.4(VOUT) U29.4(VOUT)
NetC293_1: C293.1 R213.1
NetC301_1: C301.1 R272.1 U20.1(IN+)
NetC301_2: C301.2 R273.1 U20.2(IN-)
NetC342_1: D22.2(A2) J8.5 ; port TERMINAL_CAN_PHY.CANH
NetC345_2: R496.1 R497.1 ; sheet U_POWER_DCDC_CARRIER/5V_EN
NetC361_1: D23.2(A2) J8.4 ; port TERMINAL_CAN_PHY.CANL
NetDL3_A: DL3.A R105.1
NetQ1_G: Q1.G R231.2
NetQ1_S: Q1.S Q2.S U15.6(SOURCE)
NetQ2_G: Q2.G R231.1 U15.5(GATE)
NetQ3_2: Q3.2(G) R249.1 TP82.X ; port DC_IN_OFF
NetQ3_3: Q3.3(D) ; port ~{DC_IN_AVAILABLE}
NetQ3_5: Q3.5(G) R230.2 R248.2
NetQ3_6: Q3.6(D) R245.2 U15.3(EN)
NetQ5_G: Q5.G R214.2
NetQ5_S: Q5.S Q6.S U29.6(SOURCE)
NetQ6_G: Q6.G R214.1 U29.5(GATE)
NetR150_2: R150.2 ; port 1V8_PG, sheet U_POWER_DCDC_CARRIER/1V8_PG
NetR215_1: R215.1 U29.3(EN) ; port POWER_SWITCH_USB_EN
NetR232_2: R232.2 R233.2 U20.7(A0)
NetR248_1: R248.1 R397.2
NetR336_2: R336.2 ; sheet U_LOAD_SWITCH_5V/ON
NetR337_2: R337.2 ; sheet U_LOAD_SWITCH_5V/ON
NetR338_2: R338.2 R339.1
NetR339_2: R339.2 ; sheet U_LOAD_SWITCH_5V/ILIM
NetR340_2: R340.2 R341.1
NetR341_2: R341.2 ; sheet U_LOAD_SWITCH_5V/ILIM
NetR397_1: R397.1 R472.2
NetU18_5: port 1V28_PG, sheet U_POWER_DCDC_CARRIER/1V28_PG
NetU20_8: U20.8(~{ALERT}) ; port INA_ALERT_3V3

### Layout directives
net class HIGH_CLEARANCE: 7V-24V, NetC76_1, NetC256_1, NetC256_2, NetC293_1, PA_VBUS

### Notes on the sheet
- (near DL3) POWER LED GREEN
- CYPD P0.3
- CYPD P0.1
- CYPD P4.0
- Ilim = 29100/82000 = 2.82A

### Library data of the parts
C221 C222 = C0199-A.1: CAP CHIP 0805 47uF 20% 6.3V X5R; Manufacturer: KEMET; Code Arduino: C0199
C256 C293 = C0209-A.1: CAP CHIP 0805 10nF 250V X7R; Manufacturer: Murata; Tolerance: 10%; Code Arduino: C0209
C292 C294 = C0158-A.3: as C73 on sheet ETH_PHY
C300 = C0113-A.6: as C4-C8 on sheet ETH_PHY
C301 = C0015-A.14: CAP CHIP 0402 100nF 10% 50V X5R; Manufacturer: Murata; Code Arduino: A5141
C339 = C0063-A.3: CAP CHIP 0603 1nF 10% 50V X7R; Manufacturer: Samsung Electro-Mechanics; Code Arduino: C0063
C340 = C0040-A.14: CAP CHIP 0603 10nF 10% 50V X7R; Manufacturer: Walsin; Code Arduino: 0142
D5 = D0070-A.2: as D2 on sheet HEADERS_UNO
D22 D23 = D0098-A.2: TVS BIDIRECTIONAL SMD Vr 24V, Vbr min 27.27V, 350W, SOD-323; V(BR) Typ (V): 26.7; Code Arduino: D0098
DL3 = L0009-A.6: LED SMD 0603 GREEN/568 15mcd 120^; Manufacturer: Liteon; Code Arduino: 2204
J5 = J0579-A.2: CONN PWR JACK TH 2.1X5.5mm 1.6mm PCB; Manufacturer: POWERWAY; Code Arduino: J0579
J8 = J0563-A.5: CONN SCREW TERMINAL 5 POS pitch 5mm height 13.6mm BLACK; Manufacturer: Degson; Code Arduino: J0563
Q1 Q2 Q5 Q6 = T0065-2: MOSFET N-CH 60V 18A PowerPAK 1212-8W 3.3x3.3mm; Manufacturer: Vishay; Code Arduino: T0065
Q3 = T0011-A.12: MOSFET 2N-CH 60V 0.32A SOT363; Manufacturer: Diodes Inc.; Device Type: Mosfet 2N-CH SMD; Code Arduino: A5500
R21 R22 = R0323-A.1: RES CHIP 0805 0R 1% 1/8W; Manufacturer: YAGEO; Code Arduino: R0323; Power: 125mW; Temperature coefficient: 0ppm
R105 = R0149-A.21: RES CHIP 0201 330R 1% 1/20W; Manufacturer: Yageo; Power: 50mW; Code Arduino: R0149; Temperature coefficient: 200ppm
R150 R265 = R0145-A.21: RES CHIP 0201 10k 1% 1/20W; Manufacturer: Yageo; Power: 50mW; Temperature coefficient: 200ppm; Code Arduino: R0145
R212 R213 = R0130-A.14: RES CHIP 0805 100R 1% 1/8W 100ppm; Manufacturer: YAGEO; Power: 125mW; Code Arduino: R0130
R214 R231 = R0188-A.20: RES CHIP 0603 10R 1% 1/10W; Manufacturer: Vishay; Temperature coefficient: 100ppm; Code Arduino: R0188; Power: 100mW
R215 R233 R249 = R0151-A.21: as R62-R68 on sheet ETH_PHY
R229 = R0132-A.12: RES CHIP 0805 2mR 1% 1/2W; Manufacturer: ROHM Semiconductor; Power: 500mW; Code Arduino: A5411; Temperature coefficient: 150ppm
R230 R245 = R0001-A.24: RES CHIP 0402 100k 1% 1/16W; Manufacturer: Vishay; Power: 62.5mW; Code Arduino: 0134; Temperature coefficient: 100ppm
R232 R336 R337 R496 R497 = R0140-A.21: as R284 on sheet ETH_PHY
R248 R397 R472 = R0398-A.1: RES CHIP 0201 24k 1% 1/20W; Manufacturer: YAGEO; Power: 50mW; Code Arduino: R0398; Temperature Coefficient: 200ppm
R272 R273 = R0170-A.23: RES CHIP 0402 10R 1% 1/16W; Manufacturer: YAGEO; Power: 62.5mW; Temperature coefficient: 200ppm; Code Arduino: R0170
R338 R340 = R0376-A.1: RES CHIP 0201 5k1 1% 1/20W; Manufacturer: Panasonic; Code Arduino: R0376; Power: 50mW; Temperature Coefficient: 200ppm
R339 R341 = R0398-A.1: RES CHIP 0201 24k 1% 1/20W; Manufacturer: YAGEO; Code Arduino: R0398; Power: 50mW; Temperature Coefficient: 200ppm
TP60 TP74-TP82 TP84 = UT0013-A.6: Part Number: This is not a component
U15 U29 = U0502-A.3: IC Ideal diode and load switch controller with reverse input protection, 4.2V to 60V, EN pin 1.32V, SOT23-6; Manufacturer: Kinetic Technology; Code Arduino: U0502
U20 = U0519-A.2: IC MONITOR PWR/CURR/VOLT 16bit ADC I2C SOT23-THIN8 1.6x2.9x1.1 mm; Manufacturer: Texas Instruments; Code Arduino: U0519

## Sheet POWER_DCDC_SOM.SchDoc: POWER DCDC SOM
size A3; Author: Silvio Navaretti; CompanyName: ARDUINO; DrawnBy: Silvio Navaretti; Engineer: Silvio Navaretti; Organization: ARDUINO; SheetNumber: 39; SheetTotal: 51; RevAuthor: Silvio Navaretti
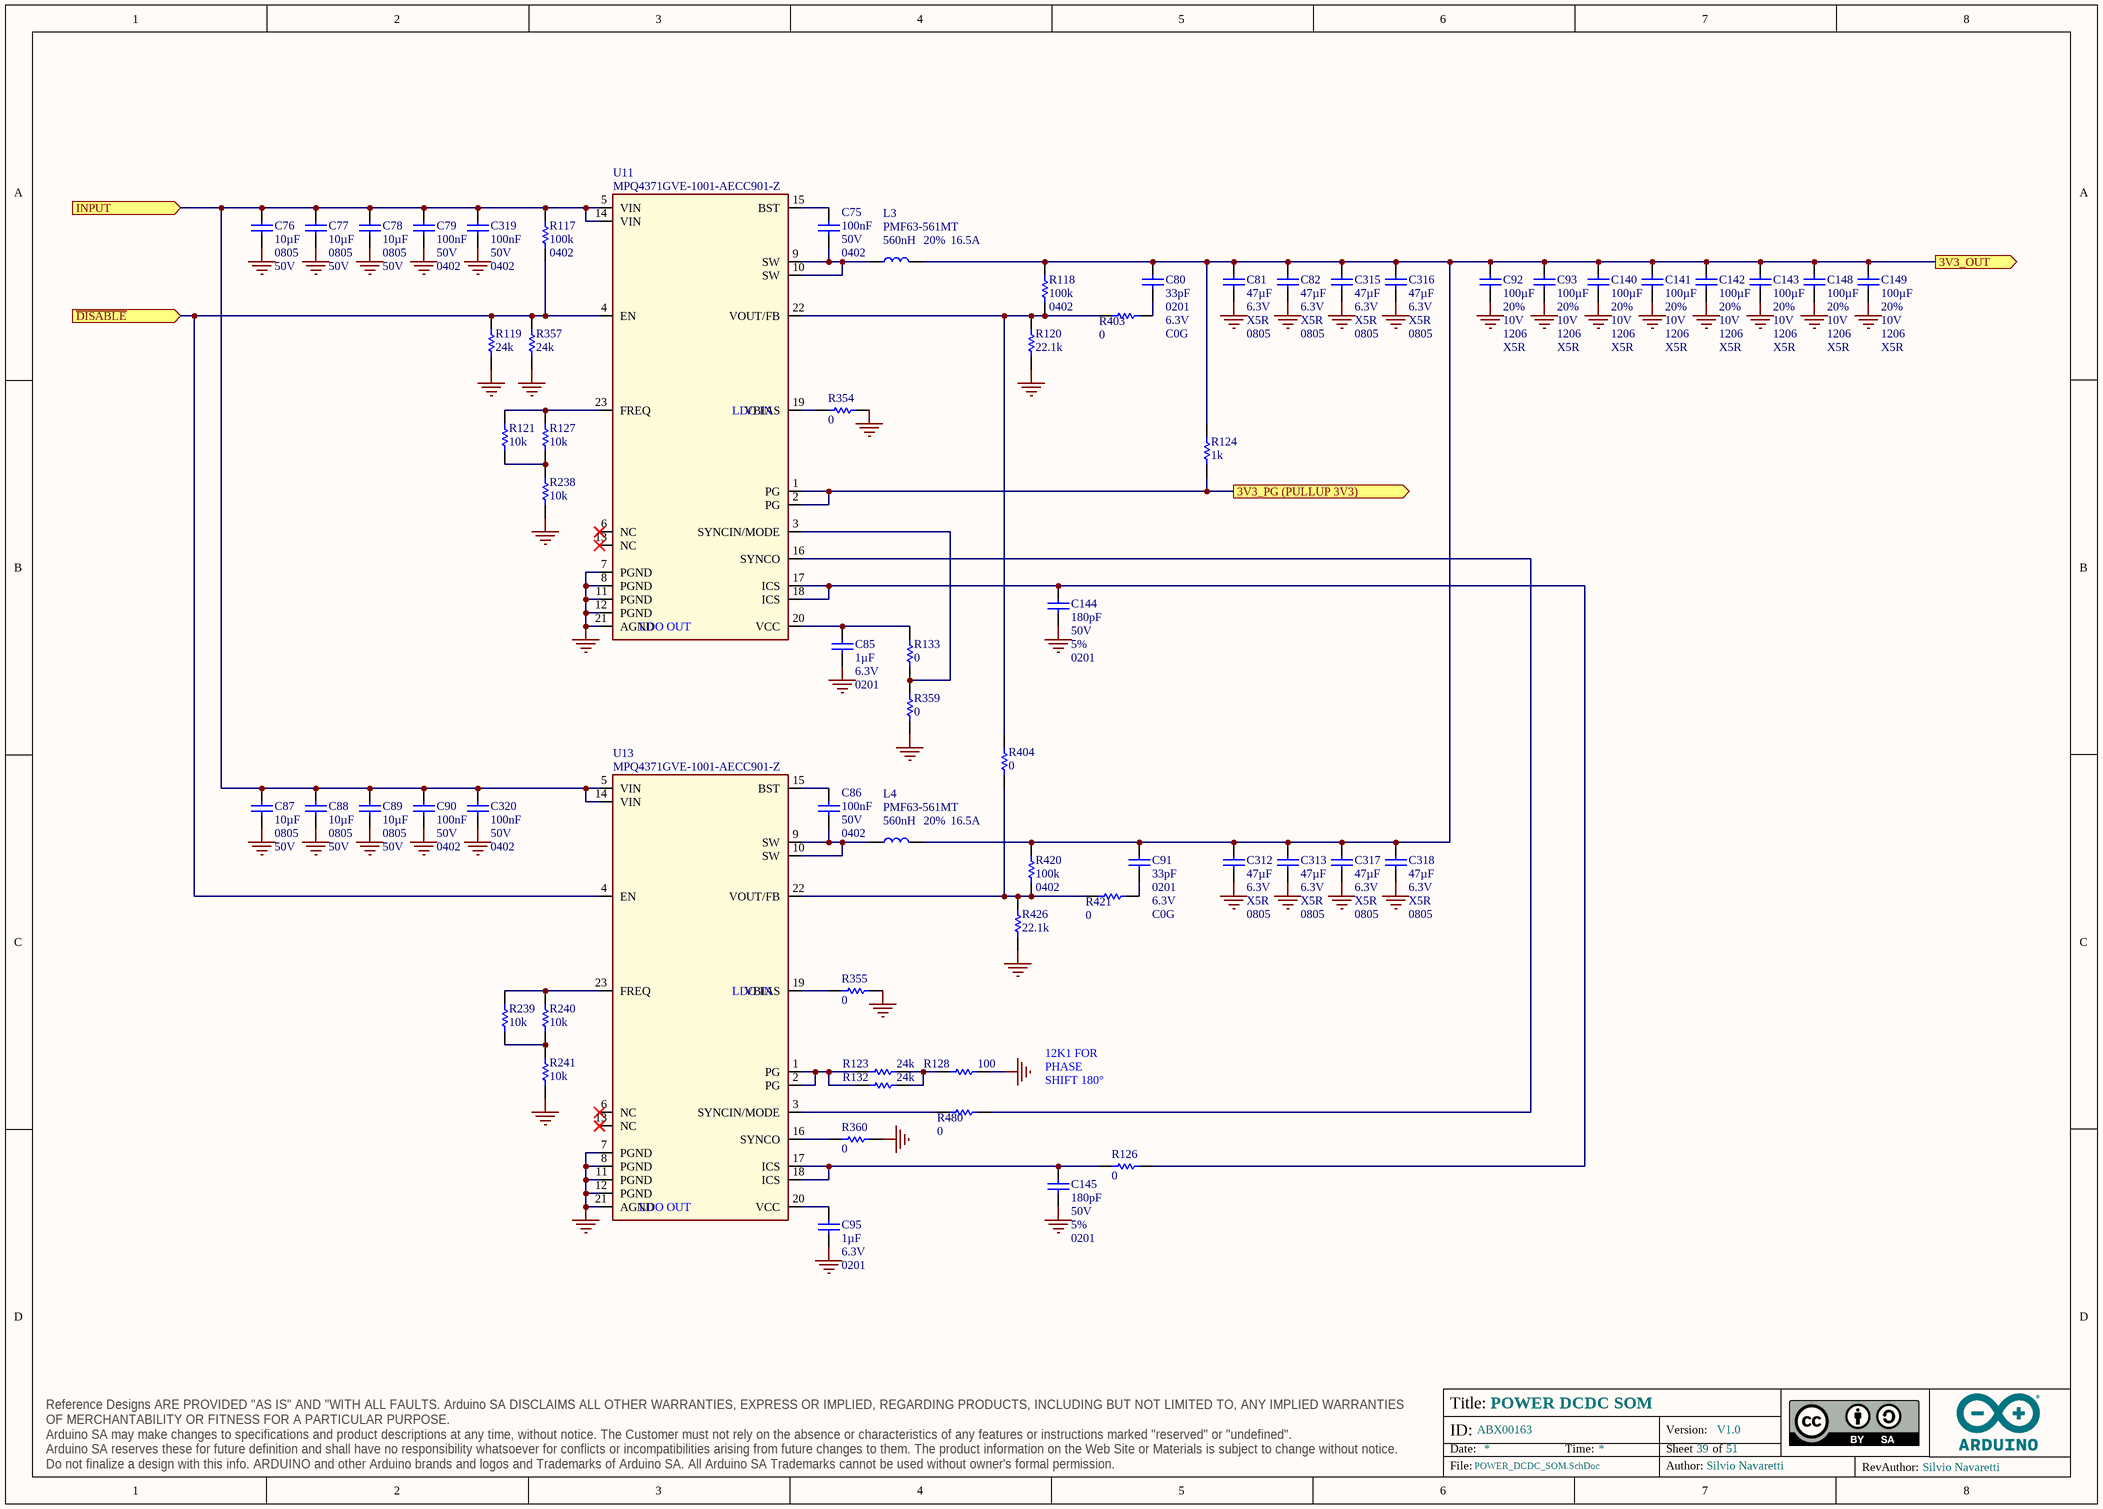
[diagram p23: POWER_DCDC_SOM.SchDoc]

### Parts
C75  value 100nF  Voltage: 50V  Case Code (Imperial): 0402  [CAP-0402]  (hidden comment: GRM155R61H104KE19D)
C76  value 10µF  Case Code (Imperial): 0805  Voltage: 50V  [CAP-0805]  (hidden comment: GRM21BR61H106ME43L)
C77  value 10µF  Case Code (Imperial): 0805  Voltage: 50V  [CAP-0805]  (hidden comment: GRM21BR61H106ME43L)
C78  value 10µF  Case Code (Imperial): 0805  Voltage: 50V  [CAP-0805]  (hidden comment: GRM21BR61H106ME43L)
C79  value 100nF  Voltage: 50V  Case Code (Imperial): 0402  [CAP-0402]  (hidden comment: GRM155R61H104KE19D)
C80  value 33pF  Case Code (Imperial): 0201  Voltage: 6.3V  Dielectric: C0G  [CAP-0201]  (hidden comment: GJM0335C0J330JB01J)
C81  value 47µF  Voltage: 6.3V  Dielectric: X5R  Case Code (Imperial): 0805  [CAP-0805]  (hidden comment: C0805C476M9PAC7800)
C82  value 47µF  Voltage: 6.3V  Dielectric: X5R  Case Code (Imperial): 0805  [CAP-0805]  (hidden comment: C0805C476M9PAC7800)
C85  value 1µF  Voltage: 6.3V  Case Code (Imperial): 0201  [CAP-0201]  (hidden comment: GRM033R60J105MEA2D)
C86  value 100nF  Voltage: 50V  Case Code (Imperial): 0402  [CAP-0402]  (hidden comment: GRM155R61H104KE19D)
C87  value 10µF  Case Code (Imperial): 0805  Voltage: 50V  [CAP-0805]  (hidden comment: GRM21BR61H106ME43L)
C88  value 10µF  Case Code (Imperial): 0805  Voltage: 50V  [CAP-0805]  (hidden comment: GRM21BR61H106ME43L)
C89  value 10µF  Case Code (Imperial): 0805  Voltage: 50V  [CAP-0805]  (hidden comment: GRM21BR61H106ME43L)
C90  value 100nF  Voltage: 50V  Case Code (Imperial): 0402  [CAP-0402]  (hidden comment: GRM155R61H104KE19D)
C91  value 33pF  Case Code (Imperial): 0201  Voltage: 6.3V  Dielectric: C0G  [CAP-0201]  (hidden comment: GJM0335C0J330JB01J)
C92  value 100µF  Tolerance: 20%  Voltage: 10V  Case Code (Imperial): 1206  Dielectric: X5R  [CAP-1206]  (hidden comment: GRM31CR61A107MEA8L)
C93  value 100µF  Tolerance: 20%  Voltage: 10V  Case Code (Imperial): 1206  Dielectric: X5R  [CAP-1206]  (hidden comment: GRM31CR61A107MEA8L)
C95  value 1µF  Voltage: 6.3V  Case Code (Imperial): 0201  [CAP-0201]  (hidden comment: GRM033R60J105MEA2D)
C140  value 100µF  Tolerance: 20%  Voltage: 10V  Case Code (Imperial): 1206  Dielectric: X5R  [CAP-1206]  (hidden comment: GRM31CR61A107MEA8L)
C141  value 100µF  Tolerance: 20%  Voltage: 10V  Case Code (Imperial): 1206  Dielectric: X5R  [CAP-1206]  (hidden comment: GRM31CR61A107MEA8L)
C142  value 100µF  Tolerance: 20%  Voltage: 10V  Case Code (Imperial): 1206  Dielectric: X5R  [CAP-1206]  (hidden comment: GRM31CR61A107MEA8L)
C143  value 100µF  Tolerance: 20%  Voltage: 10V  Case Code (Imperial): 1206  Dielectric: X5R  [CAP-1206]  (hidden comment: GRM31CR61A107MEA8L)
C144  value 180pF  Voltage: 50V  Tolerance: 5%  Case Code (Imperial): 0201  [CAP-0201]  (hidden comment: GRM0335C1H181JA01D)
C145  value 180pF  Voltage: 50V  Tolerance: 5%  Case Code (Imperial): 0201  [CAP-0201]  (hidden comment: GRM0335C1H181JA01D)
C148  value 100µF  Tolerance: 20%  Voltage: 10V  Case Code (Imperial): 1206  Dielectric: X5R  [CAP-1206]  (hidden comment: GRM31CR61A107MEA8L)
C149  value 100µF  Tolerance: 20%  Voltage: 10V  Case Code (Imperial): 1206  Dielectric: X5R  [CAP-1206]  (hidden comment: GRM31CR61A107MEA8L)
C312  value 47µF  Voltage: 6.3V  Dielectric: X5R  Case Code (Imperial): 0805  [CAP-0805]  (hidden comment: C0805C476M9PAC7800)
C313  value 47µF  Voltage: 6.3V  Dielectric: X5R  Case Code (Imperial): 0805  [CAP-0805]  (hidden comment: C0805C476M9PAC7800)
C315  value 47µF  Voltage: 6.3V  Dielectric: X5R  Case Code (Imperial): 0805  [CAP-0805]  (hidden comment: C0805C476M9PAC7800)
C316  value 47µF  Voltage: 6.3V  Dielectric: X5R  Case Code (Imperial): 0805  [CAP-0805]  (hidden comment: C0805C476M9PAC7800)
C317  value 47µF  Voltage: 6.3V  Dielectric: X5R  Case Code (Imperial): 0805  [CAP-0805]  (hidden comment: C0805C476M9PAC7800)
C318  value 47µF  Voltage: 6.3V  Dielectric: X5R  Case Code (Imperial): 0805  [CAP-0805]  (hidden comment: C0805C476M9PAC7800)
C319  value 100nF  Voltage: 50V  Case Code (Imperial): 0402  [CAP-0402]  (hidden comment: GRM155R61H104KE19D)
C320  value 100nF  Voltage: 50V  Case Code (Imperial): 0402  [CAP-0402]  (hidden comment: GRM155R61H104KE19D)
L3  PMF63-561MT  Inductance: 560nH  IRMS: 16.5A  Tolerance: 20%  [PMF63]
L4  PMF63-561MT  Inductance: 560nH  IRMS: 16.5A  Tolerance: 20%  [PMF63]
R117  value 100k  Case Code (Imperial): 0402  [RES-0402]  (hidden comment: CRCW0402100KFKEDC)
R118  value 100k  Case Code (Imperial): 0402  [RES-0402]  (hidden comment: CRCW0402100KFKEDC)
R119  value 24k  [RES-0201]  (hidden comment: RC0201FR-0724KL)
R120  value 22.1k  [RES-0201]  (hidden comment: RC0201FR-0722K1L)
R121  value 10k  [RES-0201]  (hidden comment: RC0201FR-0710KL)
R123  value 24k  [RES-0201]  (hidden comment: RC0201FR-0724KL)
R124  value 1k  [RES-0201]  (hidden comment: RC0201FR-071KL)
R126  value 0  [RES-0201]  (hidden comment: CRCW02010000Z0ED)
R127  value 10k  [RES-0201]  (hidden comment: RC0201FR-0710KL)
R128  value 100  [RES-0201]  (hidden comment: RC0201FR-07100RL)
R132  value 24k  [RES-0201]  (hidden comment: RC0201FR-0724KL)
R133  value 0  [RES-0201]  (hidden comment: CRCW02010000Z0ED)
R238  value 10k  [RES-0201]  (hidden comment: RC0201FR-0710KL)
R239  value 10k  [RES-0201]  (hidden comment: RC0201FR-0710KL)
R240  value 10k  [RES-0201]  (hidden comment: RC0201FR-0710KL)
R241  value 10k  [RES-0201]  (hidden comment: RC0201FR-0710KL)
R354  value 0  [RES-0201]  (hidden comment: CRCW02010000Z0ED)
R355  value 0  [RES-0201]  (hidden comment: CRCW02010000Z0ED)
R357  value 24k  [RES-0201]  (hidden comment: RC0201FR-0724KL)
R359  value 0  [RES-0201]  (hidden comment: CRCW02010000Z0ED)
R360  value 0  [RES-0201]  (hidden comment: CRCW02010000Z0ED)
R403  value 0  [RES-0201]  (hidden comment: CRCW02010000Z0ED)
R404  value 0  [RES-0201]  (hidden comment: CRCW02010000Z0ED)
R420  value 100k  Case Code (Imperial): 0402  [RES-0402]  (hidden comment: CRCW0402100KFKEDC)
R421  value 0  [RES-0201]  (hidden comment: CRCW02010000Z0ED)
R426  value 22.1k  [RES-0201]  (hidden comment: RC0201FR-0722K1L)
R480  value 0  [RES-0201]  (hidden comment: CRCW02010000Z0ED)
U11  MPQ4371GVE-1001-AECC901-Z  [MPQ4371GVE-1001-AECC901-Z]
U13  MPQ4371GVE-1001-AECC901-Z  [MPQ4371GVE-1001-AECC901-Z]

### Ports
3V3_OUT (out), 3V3_PG (PULLUP 3V3) (out), INPUT (in), ~{DISABLE} (in)

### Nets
+3V3: C80.2 C81.2 C82.2 C91.2 C92.1 C93.1 C140.1 C141.1 C142.1 C143.1 C148.1 C149.1 C312.2 C313.2 C315.2 C316.2 C317.2 C318.2 L3.2 L4.2 R118.1 R124.1 R420.1 ; port 3V3_OUT
GND: C76.2 C77.2 C78.2 C79.2 C81.1 C82.1 C85.1 C87.2 C88.2 C89.2 C90.2 C92.2 C93.2 C95.1 C140.2 C141.2 C142.2 C143.2 C144.1 C145.1 C148.2 C149.2 C312.1 C313.1 C315.1 C316.1 C317.1 C318.1 C319.2 C320.2 R119.1 R120.1 R128.2 R238.1 R241.1 R354.1 R355.1 R357.1 R359.1 R360.1 R426.1 U11.7(PGND) U11.8(PGND) U11.11(PGND) U11.12(PGND) U11.21(AGND) U13.7(PGND) U13.8(PGND) U13.11(PGND) U13.12(PGND) U13.21(AGND)
3V3_PG (PULLUP 3V3): R124.2 U11.1(PG) U11.2(PG) ; port 3V3_PG (PULLUP 3V3)
~{POWER_DISABLE_7-24V}: R117.2 R119.2 R357.2 U11.4(EN) U13.4(EN) ; port ~{DISABLE}
NetC75_1: C75.1 U11.15(BST)
NetC75_2: C75.2 L3.1 U11.9(SW) U11.10(SW)
NetC76_1: C76.1 C77.1 C78.1 C79.1 C87.1 C88.1 C89.1 C90.1 C319.1 C320.1 R117.1 U11.5(VIN) U11.14(VIN) U13.5(VIN) U13.14(VIN) ; port INPUT
NetC80_1: C80.1 R403.2
NetC85_2: C85.2 R133.2 U11.20(VCC)
NetC86_1: C86.1 U13.15(BST)
NetC86_2: C86.2 L4.1 U13.9(SW) U13.10(SW)
NetC91_1: C91.1 R421.2
NetC95_2: C95.2 U13.20(VCC)
NetC144_2: C144.2 R126.1 U11.17(ICS) U11.18(ICS)
NetC145_2: C145.2 R126.2 U13.17(ICS) U13.18(ICS)
NetR118_2: R118.2 R120.2 R403.1 R404.1 U11.22(VOUT/FB)
NetR121_1: R121.1 R127.1 R238.2
NetR121_2: R121.2 R127.2 U11.23(FREQ)
NetR123_1: R123.1 R128.1 R132.1
NetR123_2: R123.2 R132.2 U13.1(PG) U13.2(PG)
NetR133_1: R133.1 R359.2 U11.3(SYNCIN/MODE)
NetR239_1: R239.1 R240.1 R241.2
NetR239_2: R239.2 R240.2 U13.23(FREQ)
NetR354_2: R354.2 U11.19(VBIAS)
NetR355_2: R355.2 U13.19(VBIAS)
NetR360_2: R360.2 U13.16(SYNCO)
NetR404_2: R404.2 R420.2 R421.1 R426.2 U13.22(VOUT/FB)
NetR480_1: R480.1 U13.3(SYNCIN/MODE)
NetR480_2: R480.2 U11.16(SYNCO)

Not connected (* = marked no-connect by the designer): U11 6(NC)* 13(NC)*; U13 6(NC)* 13(NC)*

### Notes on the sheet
- 12K1 FOR PHASE SHIFT 180°

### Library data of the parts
C75 C79 C86 C90 C319 C320 = C0015-A.14: as C301 on sheet POWER
C76-C78 C87-C89 = C0158-A.3: as C73 on sheet ETH_PHY
C80 C91 = C0114-A.6: CAP CHIP 0201 33pF 5% 6.3V C0G; Manufacturer: Murata Electronics; Code Arduino: C0114
C81 C82 C312 C313 C315-C318 = C0199-A.1: as C221 on sheet POWER
C85 C95 = C0002-A.15: as C9 on sheet ETH_PHY
C92 C93 C140-C143 C148 C149 = C0166-A.1: CAP CHIP 1206 100uF 20% 10V X5R; Manufacturer: Murata; Code Arduino: C0166
C144 C145 = C0198-A.1: CAP CHIP 0201 180pF 5% 50V C0G; Manufacturer: Murata; Code Arduino: C0198
L3 L4 = I0124-A.1: IND 0.56uH 20%, max 5mR, IRMS 16.5A, Isat 25.5A, 7.3x6.6x3mm; Manufacturer: K-WELL; Code Arduino: I0124; DCR max: 5m
R117 R118 R420 = R0001-A.24: as R230 on sheet POWER
R119 R123 R132 R357 = R0398-A.1: as R248 on sheet POWER
R120 R426 = R0396-A.1: RES CHIP 0201 22k1 1% 1/20W; Manufacturer: YAGEO; Code Arduino: R0396; Temperature Coefficient: 200ppm; Power: 50mW
R121 R127 R238-R241 = R0145-A.21: as R150 on sheet POWER
R124 = R0195-A.22: RES CHIP 0201 1k 1% 1/20W; Manufacturer: Yageo; Power: 50mW; Temperature coefficient: 200ppm; Code Arduino: R0195
R126 R133 R354 R355 R359 R360 R403 R404 R421 R480 = R0140-A.21: as R284 on sheet ETH_PHY
R128 = R0235-A.13: RES CHIP 0201 100R 1% 1/20W; Manufacturer: YAGEO; Power: 50mW; Temperature coefficient: 200ppm; Code Arduino: R0235
U11 U13 = U0503-A.7: IC Buck Vin 36V, Vout ADJ, Iout max 11A, with FSS, multi phase, QFN23 4x5mm; Manufacturer: MPS; Code Arduino: U0503

## Sheet POWER_REGULATORS_CARRIER.SchDoc: POWER REGULATORS CARRIER
size A3; Author: Silvio Navaretti; CompanyName: ARDUINO; DrawnBy: Silvio Navaretti; Engineer: Silvio Navaretti; Organization: ARDUINO; SheetNumber: 40; SheetTotal: 51; RevAuthor: Silvio Navaretti
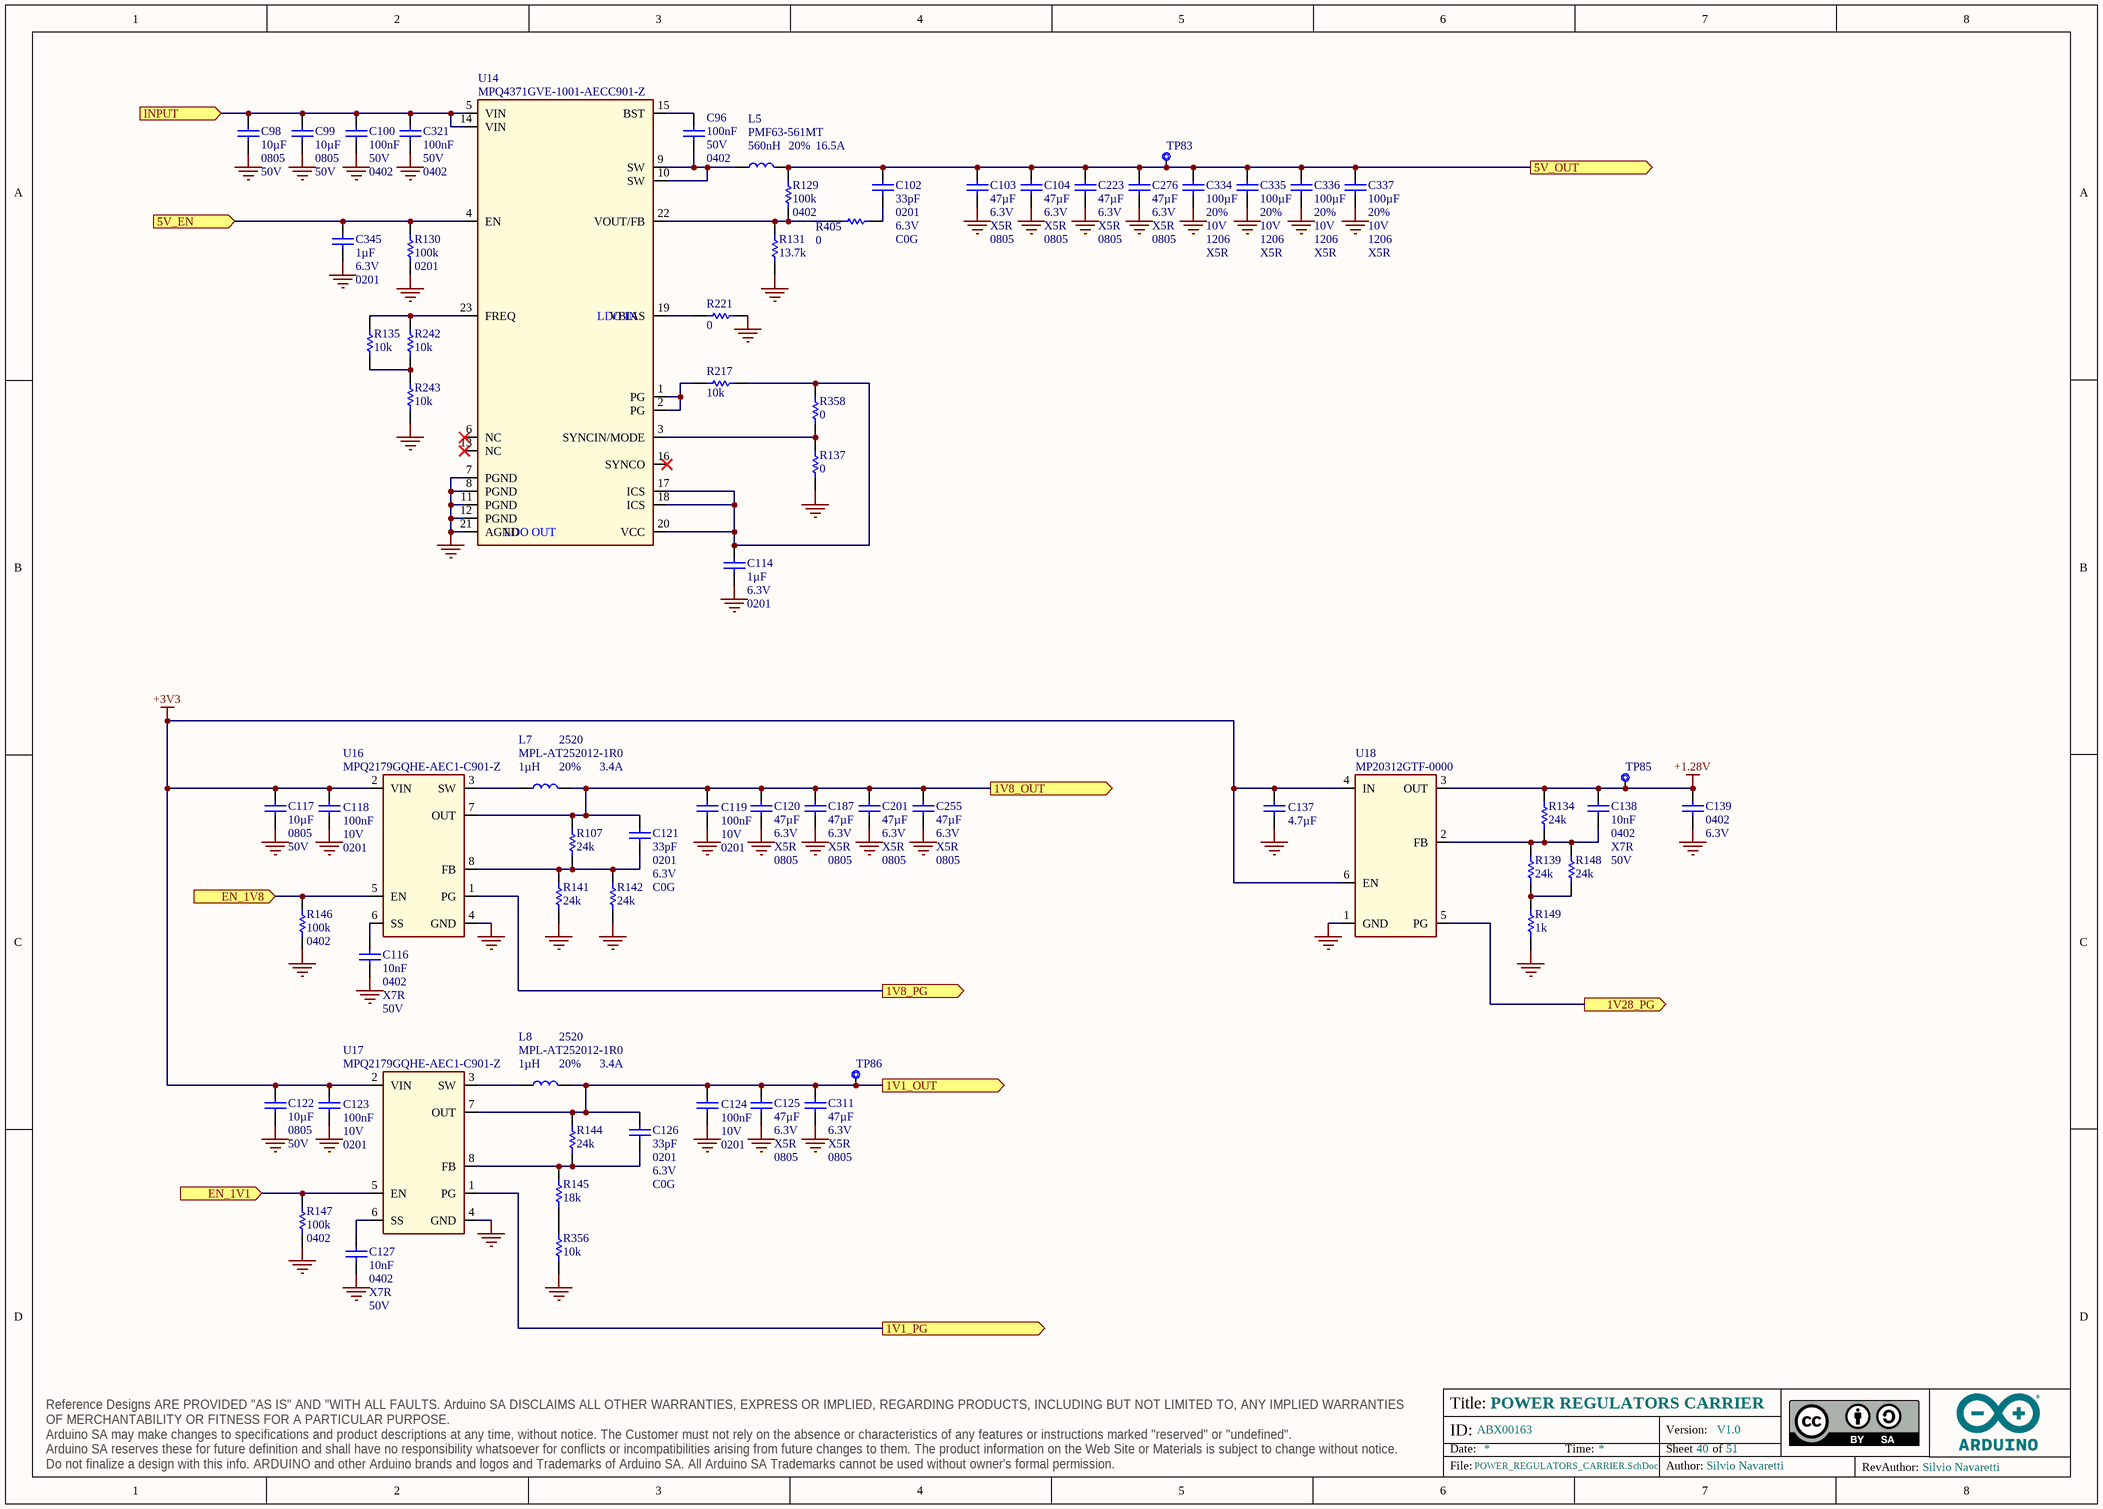
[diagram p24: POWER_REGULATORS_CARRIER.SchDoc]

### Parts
C96  value 100nF  Voltage: 50V  Case Code (Imperial): 0402  [CAP-0402]  (hidden comment: GRM155R61H104KE19D)
C98  value 10µF  Case Code (Imperial): 0805  Voltage: 50V  [CAP-0805]  (hidden comment: GRM21BR61H106ME43L)
C99  value 10µF  Case Code (Imperial): 0805  Voltage: 50V  [CAP-0805]  (hidden comment: GRM21BR61H106ME43L)
C100  value 100nF  Voltage: 50V  Case Code (Imperial): 0402  [CAP-0402]  (hidden comment: GRM155R61H104KE19D)
C102  value 33pF  Case Code (Imperial): 0201  Voltage: 6.3V  Dielectric: C0G  [CAP-0201]  (hidden comment: GJM0335C0J330JB01J)
C103  value 47µF  Voltage: 6.3V  Dielectric: X5R  Case Code (Imperial): 0805  [CAP-0805]  (hidden comment: C0805C476M9PAC7800)
C104  value 47µF  Voltage: 6.3V  Dielectric: X5R  Case Code (Imperial): 0805  [CAP-0805]  (hidden comment: C0805C476M9PAC7800)
C114  value 1µF  Voltage: 6.3V  Case Code (Imperial): 0201  [CAP-0201]  (hidden comment: GRM033R60J105MEA2D)
C116  value 10nF  Case Code (Imperial): 0402  Dielectric: X7R  Voltage: 50V  [CAP-0402]  (hidden comment: C1005B103K500NT)
C117  value 10µF  Case Code (Imperial): 0805  Voltage: 50V  [CAP-0805]  (hidden comment: GRM21BR61H106ME43L)
C118  value 100nF  Voltage: 10V  Case Code (Imperial): 0201  [CAP-0201]  (hidden comment: CL03A104KP3NNNC)
C119  value 100nF  Voltage: 10V  Case Code (Imperial): 0201  [CAP-0201]  (hidden comment: CL03A104KP3NNNC)
C120  value 47µF  Voltage: 6.3V  Dielectric: X5R  Case Code (Imperial): 0805  [CAP-0805]  (hidden comment: C0805C476M9PAC7800)
C121  value 33pF  Case Code (Imperial): 0201  Voltage: 6.3V  Dielectric: C0G  [CAP-0201]  (hidden comment: GJM0335C0J330JB01J)
C122  value 10µF  Case Code (Imperial): 0805  Voltage: 50V  [CAP-0805]  (hidden comment: GRM21BR61H106ME43L)
C123  value 100nF  Voltage: 10V  Case Code (Imperial): 0201  [CAP-0201]  (hidden comment: CL03A104KP3NNNC)
C124  value 100nF  Voltage: 10V  Case Code (Imperial): 0201  [CAP-0201]  (hidden comment: CL03A104KP3NNNC)
C125  value 47µF  Voltage: 6.3V  Dielectric: X5R  Case Code (Imperial): 0805  [CAP-0805]  (hidden comment: C0805C476M9PAC7800)
C126  value 33pF  Case Code (Imperial): 0201  Voltage: 6.3V  Dielectric: C0G  [CAP-0201]  (hidden comment: GJM0335C0J330JB01J)
C127  value 10nF  Case Code (Imperial): 0402  Dielectric: X7R  Voltage: 50V  [CAP-0402]  (hidden comment: C1005B103K500NT)
C137  value 4.7µF  [CAP-0402]  (hidden comment: C1005A475M6R3NT)
C138  value 10nF  Case Code (Imperial): 0402  Dielectric: X7R  Voltage: 50V  [CAP-0402]  (hidden comment: C1005B103K500NT)
C139  Case Code (Imperial): 0402  Voltage: 6.3V  [CAP-0402]  (hidden comment: C1005A475M6R3NT)
C187  value 47µF  Voltage: 6.3V  Dielectric: X5R  Case Code (Imperial): 0805  [CAP-0805]  (hidden comment: C0805C476M9PAC7800)
C201  value 47µF  Voltage: 6.3V  Dielectric: X5R  Case Code (Imperial): 0805  [CAP-0805]  (hidden comment: C0805C476M9PAC7800)
C223  value 47µF  Voltage: 6.3V  Dielectric: X5R  Case Code (Imperial): 0805  [CAP-0805]  (hidden comment: C0805C476M9PAC7800)
C255  value 47µF  Voltage: 6.3V  Dielectric: X5R  Case Code (Imperial): 0805  [CAP-0805]  (hidden comment: C0805C476M9PAC7800)
C276  value 47µF  Voltage: 6.3V  Dielectric: X5R  Case Code (Imperial): 0805  [CAP-0805]  (hidden comment: C0805C476M9PAC7800)
C311  value 47µF  Voltage: 6.3V  Dielectric: X5R  Case Code (Imperial): 0805  [CAP-0805]  (hidden comment: C0805C476M9PAC7800)
C321  value 100nF  Voltage: 50V  Case Code (Imperial): 0402  [CAP-0402]  (hidden comment: GRM155R61H104KE19D)
C334  value 100µF  Tolerance: 20%  Voltage: 10V  Case Code (Imperial): 1206  Dielectric: X5R  [CAP-1206]  (hidden comment: GRM31CR61A107MEA8L)
C335  value 100µF  Tolerance: 20%  Voltage: 10V  Case Code (Imperial): 1206  Dielectric: X5R  [CAP-1206]  (hidden comment: GRM31CR61A107MEA8L)
C336  value 100µF  Tolerance: 20%  Voltage: 10V  Case Code (Imperial): 1206  Dielectric: X5R  [CAP-1206]  (hidden comment: GRM31CR61A107MEA8L)
C337  value 100µF  Tolerance: 20%  Voltage: 10V  Case Code (Imperial): 1206  Dielectric: X5R  [CAP-1206]  (hidden comment: GRM31CR61A107MEA8L)
C345  value 1µF  Voltage: 6.3V  Case Code (Imperial): 0201  [CAP-0201]  (hidden comment: GRM033R60J105MEA2D)
L5  PMF63-561MT  Inductance: 560nH  IRMS: 16.5A  Tolerance: 20%  [PMF63]
L7  MPL-AT252012-1R0  Tolerance: 20%  Case Code (Metric): 2520  Inductance: 1µH  IRMS: 3.4A  [INDUCTOR 2520]
L8  MPL-AT252012-1R0  Tolerance: 20%  Case Code (Metric): 2520  Inductance: 1µH  IRMS: 3.4A  [INDUCTOR 2520]
R107  value 24k  [RES-0201]  (hidden comment: RC0201FR-0724KL)
R129  value 100k  Case Code (Imperial): 0402  [RES-0402]  (hidden comment: CRCW0402100KFKEDC)
R130  value 100k  Case Code (Imperial): 0201  [RES-0201]  (hidden comment: RC0201FR-07100KL)
R131  value 13.7k  [RES-0201]  (hidden comment: RC0201FR-0713K7L)
R134  value 24k  [RES-0201]  (hidden comment: RC0201FR-0724KL)
R135  value 10k  [RES-0201]  (hidden comment: RC0201FR-0710KL)
R137  value 0  [RES-0201]  (hidden comment: CRCW02010000Z0ED)
R139  value 24k  [RES-0201]  (hidden comment: RC0201FR-0724KL)
R141  value 24k  [RES-0201]  (hidden comment: RC0201FR-0724KL)
R142  value 24k  [RES-0201]  (hidden comment: RC0201FR-0724KL)
R144  value 24k  [RES-0201]  (hidden comment: RC0201FR-0724KL)
R145  value 18k  [RES-0201]  (hidden comment: RC0201FR-0718KL)
R146  value 100k  Case Code (Imperial): 0402  [RES-0402]  (hidden comment: CRCW0402100KFKEDC)
R147  value 100k  Case Code (Imperial): 0402  [RES-0402]  (hidden comment: CRCW0402100KFKEDC)
R148  value 24k  [RES-0201]  (hidden comment: RC0201FR-0724KL)
R149  value 1k  [RES-0201]  (hidden comment: RC0201FR-071KL)
R217  value 10k  [RES-0201]  (hidden comment: RC0201FR-0710KL)
R221  value 0  [RES-0201]  (hidden comment: CRCW02010000Z0ED)
R242  value 10k  [RES-0201]  (hidden comment: RC0201FR-0710KL)
R243  value 10k  [RES-0201]  (hidden comment: RC0201FR-0710KL)
R356  value 10k  [RES-0201]  (hidden comment: RC0201FR-0710KL)
R358  value 0  [RES-0201]  (hidden comment: CRCW02010000Z0ED)
R405  value 0  [RES-0201]  (hidden comment: CRCW02010000Z0ED)
TP83  Test point 1.00mm  [TP-1.00MM]  (value not drawn)  (no BOM)
TP85  Test point 1.00mm  [TP-1.00MM]  (value not drawn)  (no BOM)
TP86  Test point 1.00mm  [TP-1.00MM]  (value not drawn)  (no BOM)
U14  MPQ4371GVE-1001-AECC901-Z  [MPQ4371GVE-1001-AECC901-Z]
U16  MPQ2179GQHE-AEC1-C901-Z  [MPS QFN8 pitch 0.5mm 1.5x2x1mm]
U17  MPQ2179GQHE-AEC1-C901-Z  [MPS QFN8 pitch 0.5mm 1.5x2x1mm]
U18  MP20312GTF-0000  [SOT563]

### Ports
1V1_OUT (out), 1V1_PG (out), 1V8_OUT (out), 1V8_PG (out), 1V28_PG (out), 5V_EN (in), 5V_OUT (out), EN_1V1 (in), EN_1V8 (in), INPUT (in)

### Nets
+1.28V: C138.1 C139.1 R134.1 TP85.X U18.3(OUT)
+1V1: C124.2 C125.2 C126.2 C311.2 L8.2 R144.2 TP86.X U17.7(OUT) ; port 1V1_OUT
+3V3: C117.2 C118.2 C122.2 C123.2 C137.2 U16.2(VIN) U17.2(VIN) U18.4(IN) U18.6(EN)
+5V: C102.2 C103.2 C104.2 C223.2 C276.2 C334.1 C335.1 C336.1 C337.1 L5.2 R129.1 TP83.X ; port 5V_OUT
GND: C98.2 C99.2 C100.2 C103.1 C104.1 C114.1 C116.2 C117.1 C118.1 C119.1 C120.1 C122.1 C123.1 C124.1 C125.1 C127.2 C137.1 C139.2 C187.1 C201.1 C223.1 C255.1 C276.1 C311.1 C321.2 C334.2 C335.2 C336.2 C337.2 C345.1 R130.2 R131.1 R137.1 R141.1 R142.1 R146.2 R147.2 R149.2 R221.1 R243.1 R356.1 U14.7(PGND) U14.8(PGND) U14.11(PGND) U14.12(PGND) U14.21(AGND) U16.4(GND) U17.4(GND) U18.1(GND)
SOM_VREG_MDPX3_1P8: R146.1 R147.1 U16.5(EN) U17.5(EN) ; port EN_1V8, port EN_1V1
1V05_PG (PULLUP 1V8): U17.1(PG) ; port 1V1_PG
NetC76_1: C98.1 C99.1 C100.1 C321.1 U14.5(VIN) U14.14(VIN) ; port INPUT
NetC96_1: C96.1 U14.15(BST)
NetC96_2: C96.2 L5.1 U14.9(SW) U14.10(SW)
NetC102_1: C102.1 R405.2
NetC114_2: C114.2 R217.1 R358.2 U14.17(ICS) U14.18(ICS) U14.20(VCC)
NetC116_1: C116.1 U16.6(SS)
NetC119_2: C119.2 C120.2 C121.2 C187.2 C201.2 C255.2 L7.2 R107.2 U16.7(OUT) ; port 1V8_OUT
NetC121_1: C121.1 R107.1 R141.2 R142.2 U16.8(FB)
NetC126_1: C126.1 R144.1 R145.2 U17.8(FB)
NetC127_1: C127.1 U17.6(SS)
NetC138_2: C138.2 R134.2 R139.2 R148.2 U18.2(FB)
NetC345_2: C345.2 R130.1 U14.4(EN) ; port 5V_EN
NetL7_1: L7.1 U16.3(SW)
NetL8_1: L8.1 U17.3(SW)
NetR129_2: R129.2 R131.2 R405.1 U14.22(VOUT/FB)
NetR135_1: R135.1 R242.1 R243.2
NetR135_2: R135.2 R242.2 U14.23(FREQ)
NetR137_2: R137.2 R358.1 U14.3(SYNCIN/MODE)
NetR139_1: R139.1 R148.1 R149.1
NetR145_1: R145.1 R356.2
NetR150_2: U16.1(PG) ; port 1V8_PG
NetR217_2: R217.2 U14.1(PG) U14.2(PG)
NetR221_2: R221.2 U14.19(VBIAS)
NetU18_5: U18.5(PG) ; port 1V28_PG

Not connected (* = marked no-connect by the designer): U14 6(NC)* 13(NC)* 16(SYNCO)*

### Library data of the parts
C96 C100 C321 = C0015-A.14: as C301 on sheet POWER
C98 C99 C117 C122 = C0158-A.3: as C73 on sheet ETH_PHY
C102 C121 C126 = C0114-A.6: as C80 on sheet POWER_DCDC_SOM
C103 C104 C120 C125 C187 C201 C223 C255 C276 C311 = C0199-A.1: as C221 on sheet POWER
C114 C345 = C0002-A.15: as C9 on sheet ETH_PHY
C116 C127 C138 = C0009-A.15: CAP CHIP 0402 10nF 10% 50V X7R; Manufacturer: Hottech; Code Arduino: 0165
C118 C119 C123 C124 = C0113-A.6: as C4-C8 on sheet ETH_PHY
C137 = C0037-A.14: CAP CHIP 0402 4.7uF 20% 6V3 X5R; Manufacturer: Hottech; Code Arduino: 0833; Voltage: 6.3V
C139 = C0037-A.14: CAP CHIP 0402 4.7uF 20% 6V3 X5R; Manufacturer: Hottech; Value: 4.7µF; Code Arduino: 0833
C334-C337 = C0166-A.1: as C92 on sheet POWER_DCDC_SOM
L5 = I0124-A.1: as L3 on sheet POWER_DCDC_SOM
L7 L8 = I0127-A.3: IND SMD 1uH 20% ISAT 4.5A IRMS 3.4A 55mR MAX 2.5x2.1.2mm; Manufacturer: MPS; DCR max: 55m; Code Arduino: I0127; Resonant frequency: 88MHz
R107 R139 R141 R142 R144 R148 = R0398-A.1: as R248 on sheet POWER
R129 R146 R147 = R0001-A.24: as R230 on sheet POWER
R130 = R0146-A.21: RES CHIP 0201 100k 1% 1/20W; Manufacturer: Yageo; Power: 50mW; Code Arduino: R0146; Temperature coefficient: 200ppm
R131 = R0395-A.1: RES CHIP 0201 13k7 1% 1/20W; Manufacturer: YAGEO; Power: 50mW; Temperature Coefficient: 200ppm; Code Arduino: R0395
R134 = R0398-A.1: RES CHIP 0201 24k 1% 1/20W; Manufacturer: YAGEO; Power: 50mW; Temperature Coefficient: 200ppm; Code Arduino: R0398
R135 R242 R243 = R0145-A.21: as R150 on sheet POWER
R137 R221 R358 R405 = R0140-A.21: as R284 on sheet ETH_PHY
R145 = R0399-A.1: as R342 on sheet ETH_PHY
R149 = R0195-A.22: as R124 on sheet POWER_DCDC_SOM
R217 = R0145-A.21: RES CHIP 0201 10k 1% 1/20W; Manufacturer: Yageo; Temperature coefficient: 200ppm; Code Arduino: R0145; Power: 50mW
R356 = R0145-A.21: RES CHIP 0201 10k 1% 1/20W; Manufacturer: Yageo; Power: 50mW; Code Arduino: R0145; Temperature coefficient: 200ppm
TP83 TP85 TP86 = UT0013-A.6: Part Number: This is not a component
U14 = U0503-A.7: as U11 on sheet POWER_DCDC_SOM
U16 U17 = U0504-A.5: IC Buck Vin 5.5V, Vout ADJ, Iout max 3A, fsw 2.4MHz, QFN8 2x1.5mm; Manufacturer: MPS; Code Arduino: U0504
U18 = U0496-A.5: IC LDO, Vin 1.6V - 5.5V, Vout ADJ, Iout 0.5A, SOT563 1.6x1.6mm; Manufacturer: MPS; Code Arduino: U0496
